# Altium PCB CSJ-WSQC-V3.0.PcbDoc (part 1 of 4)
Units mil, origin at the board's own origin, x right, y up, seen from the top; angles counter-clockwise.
Board outline 5060 x 7131.55 mil, 4 copper layers (Top Layer, InternalPlane1, InternalPlane2, Bottom Layer); 390 components, 277 nets, 1183 pads, 601 vias.
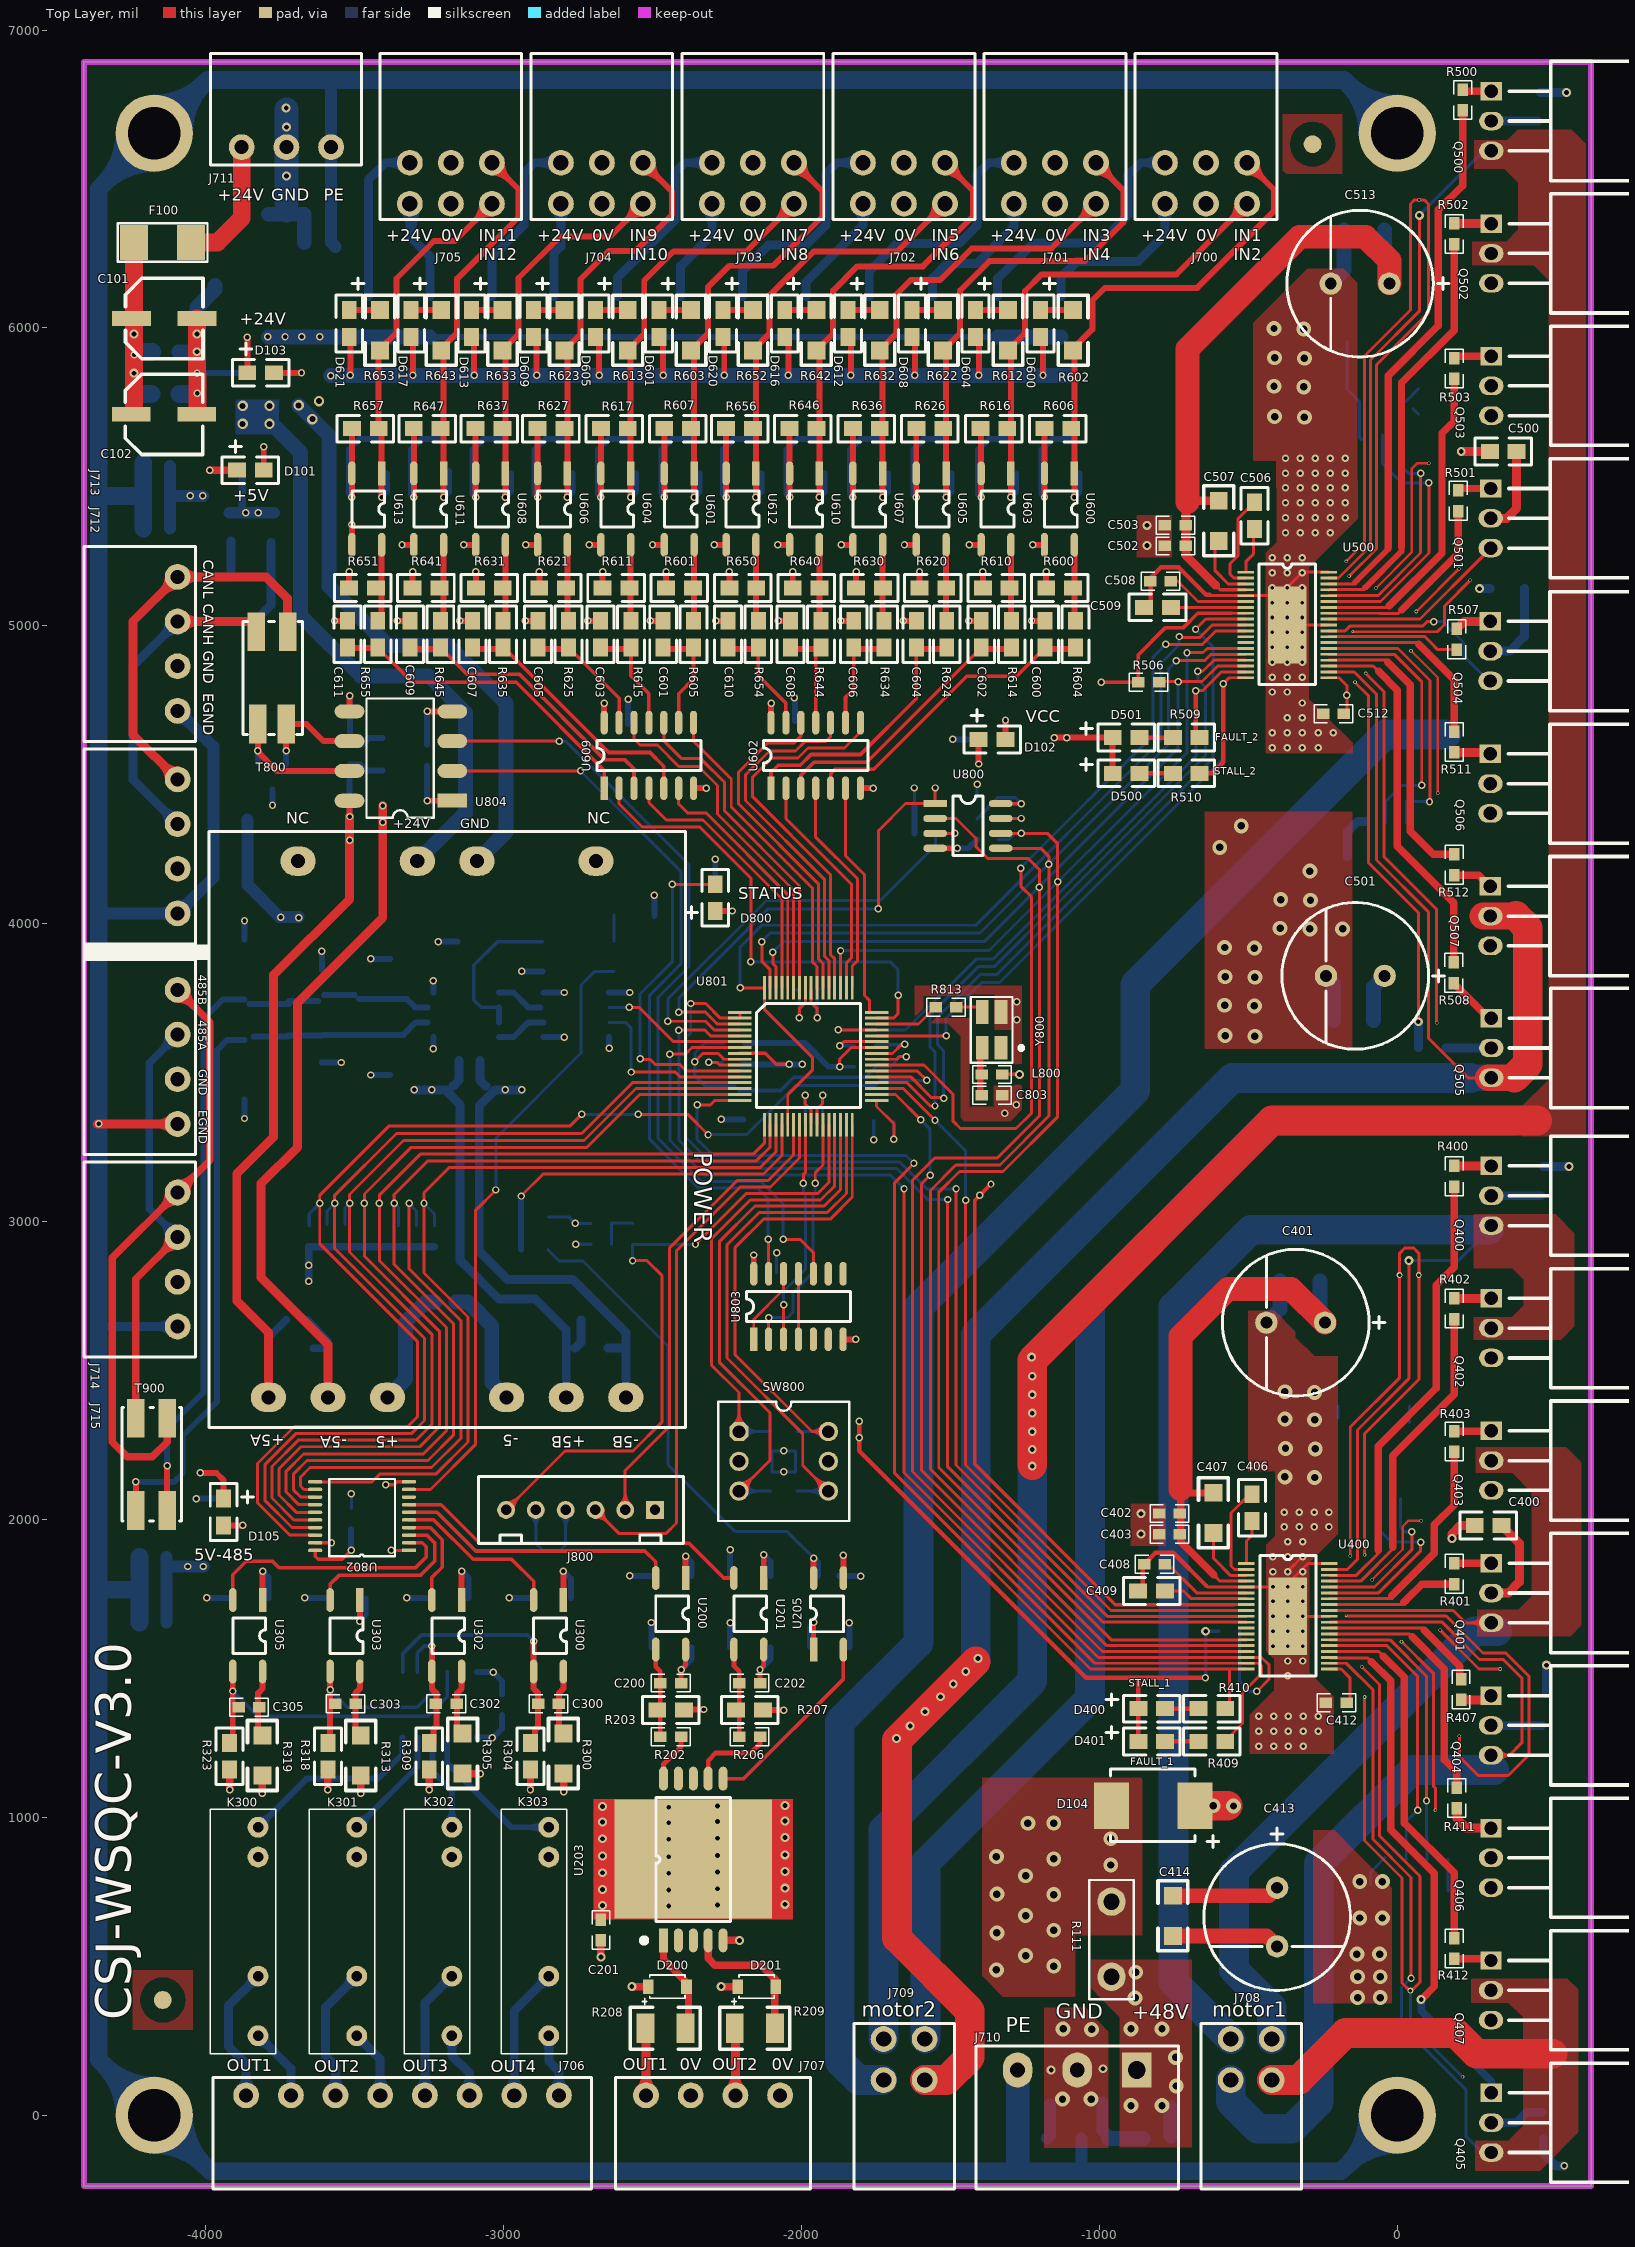
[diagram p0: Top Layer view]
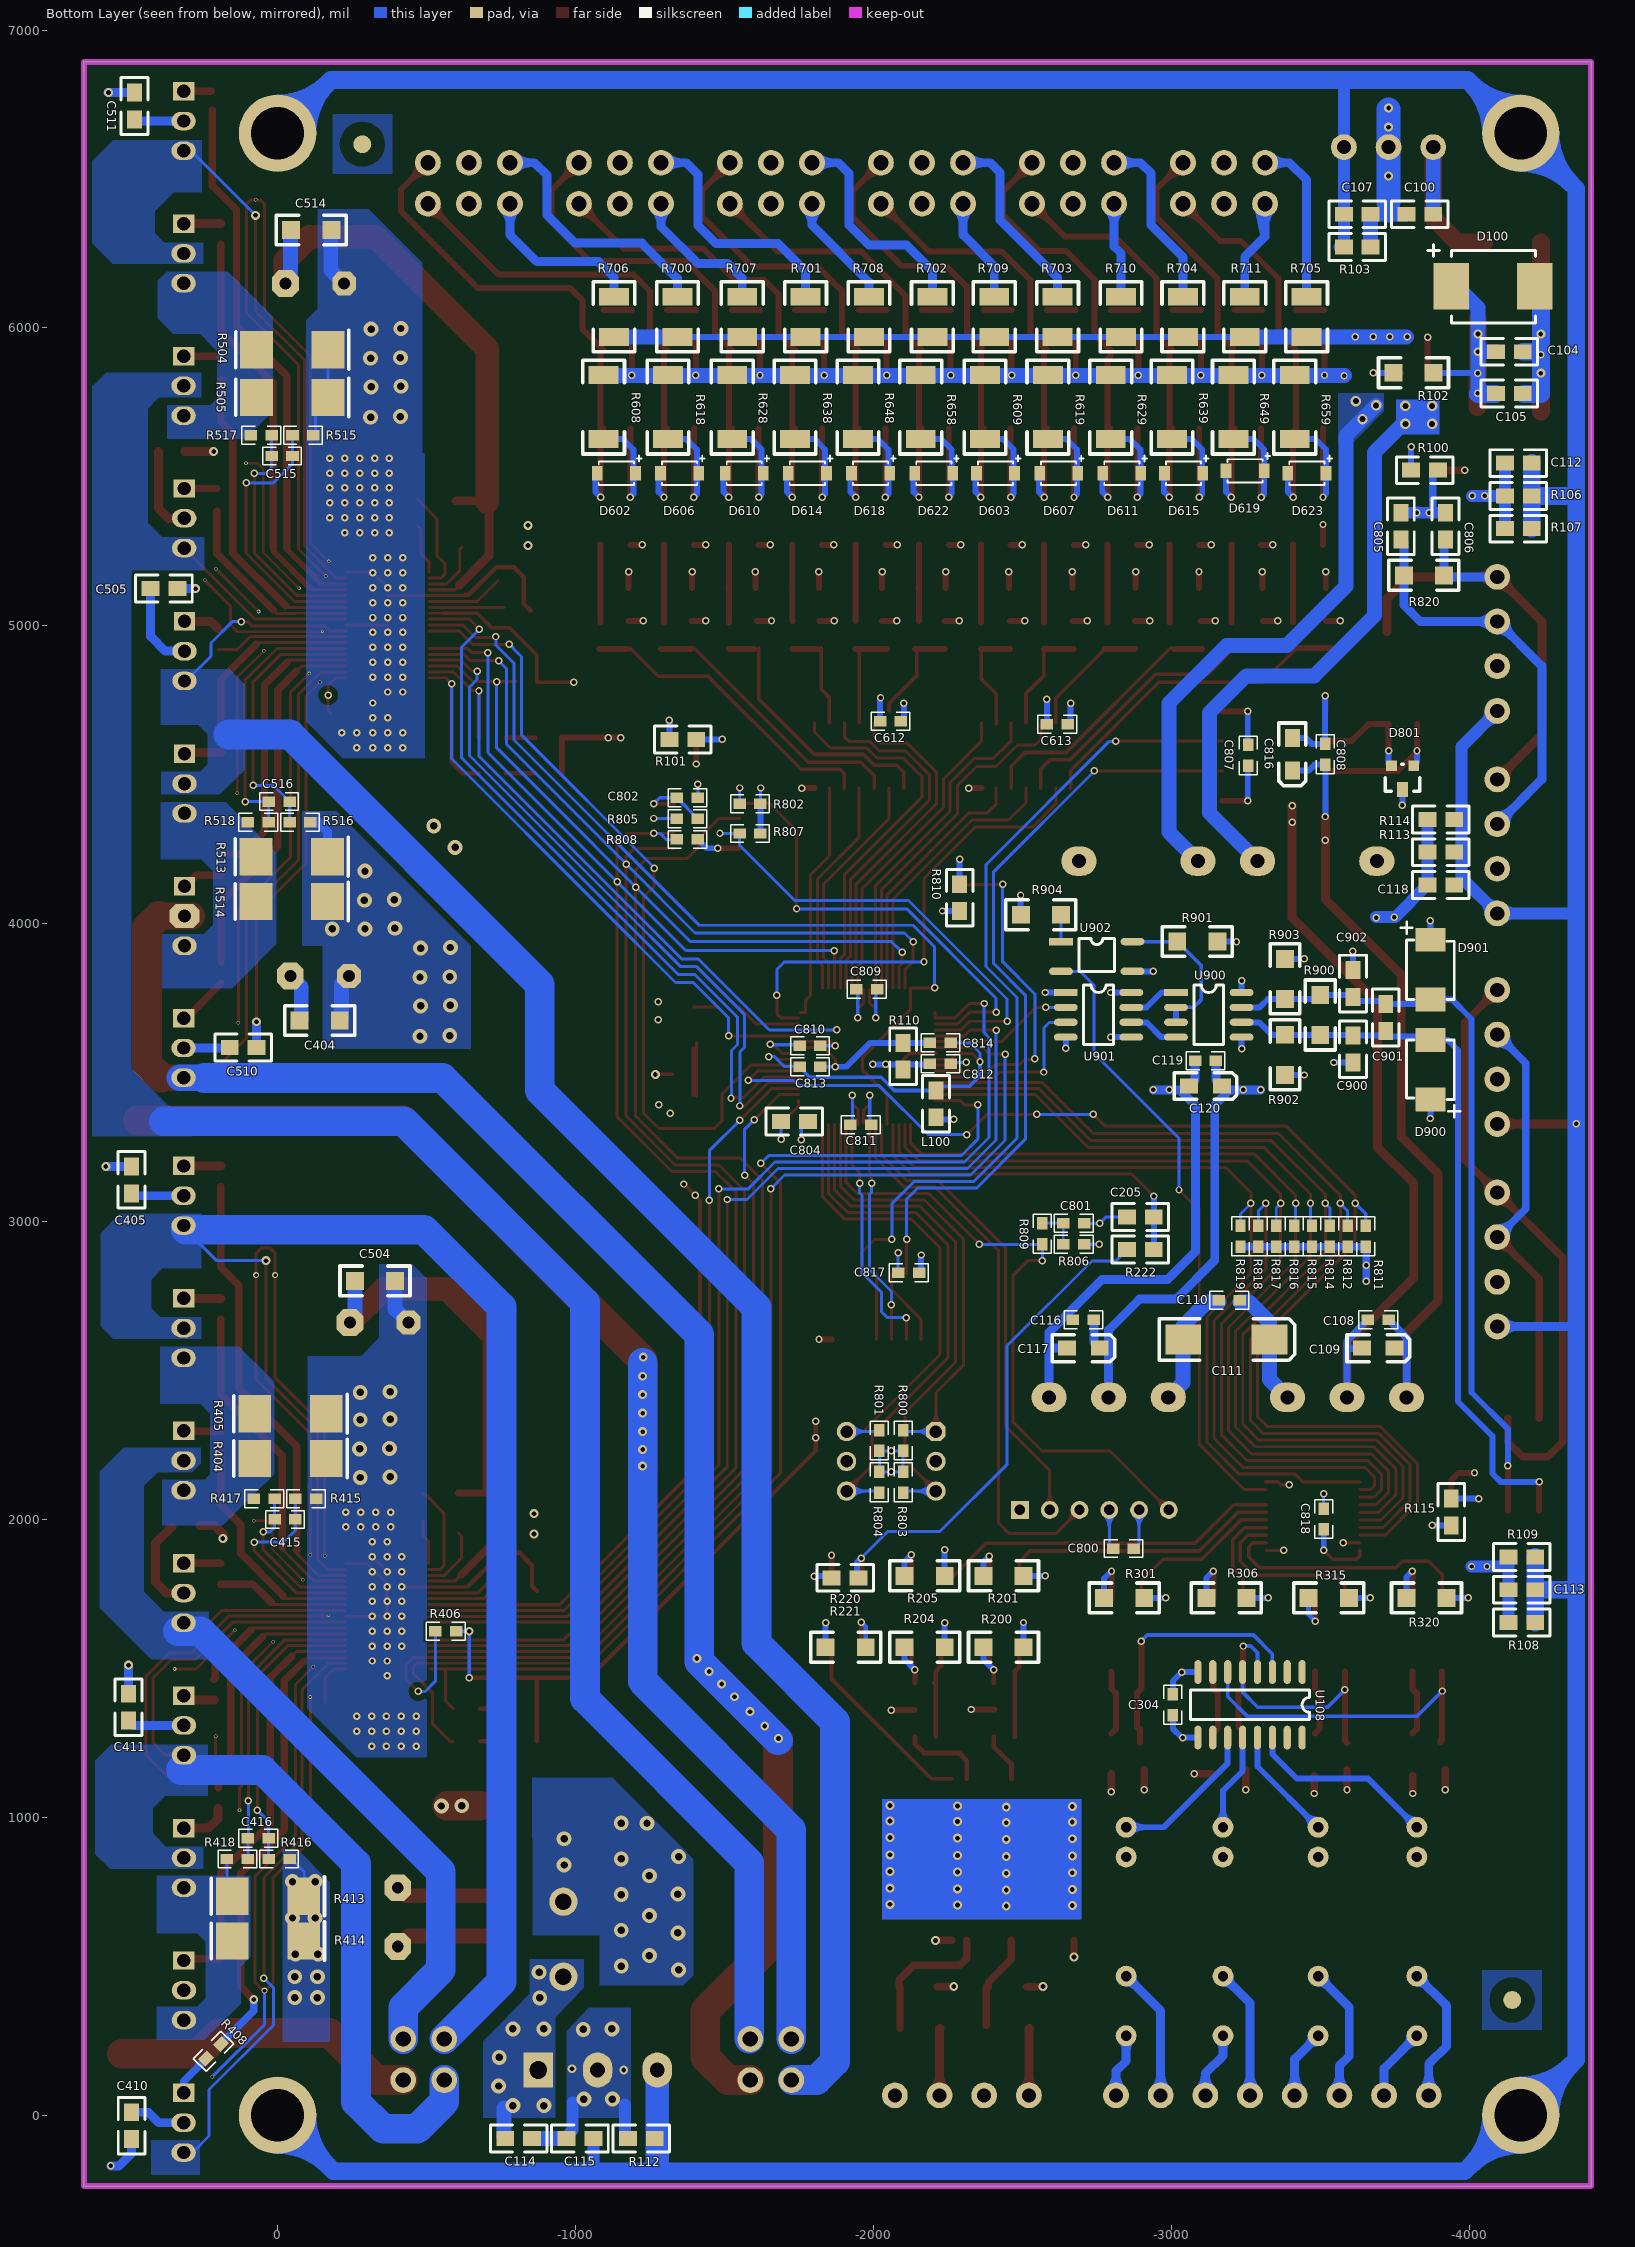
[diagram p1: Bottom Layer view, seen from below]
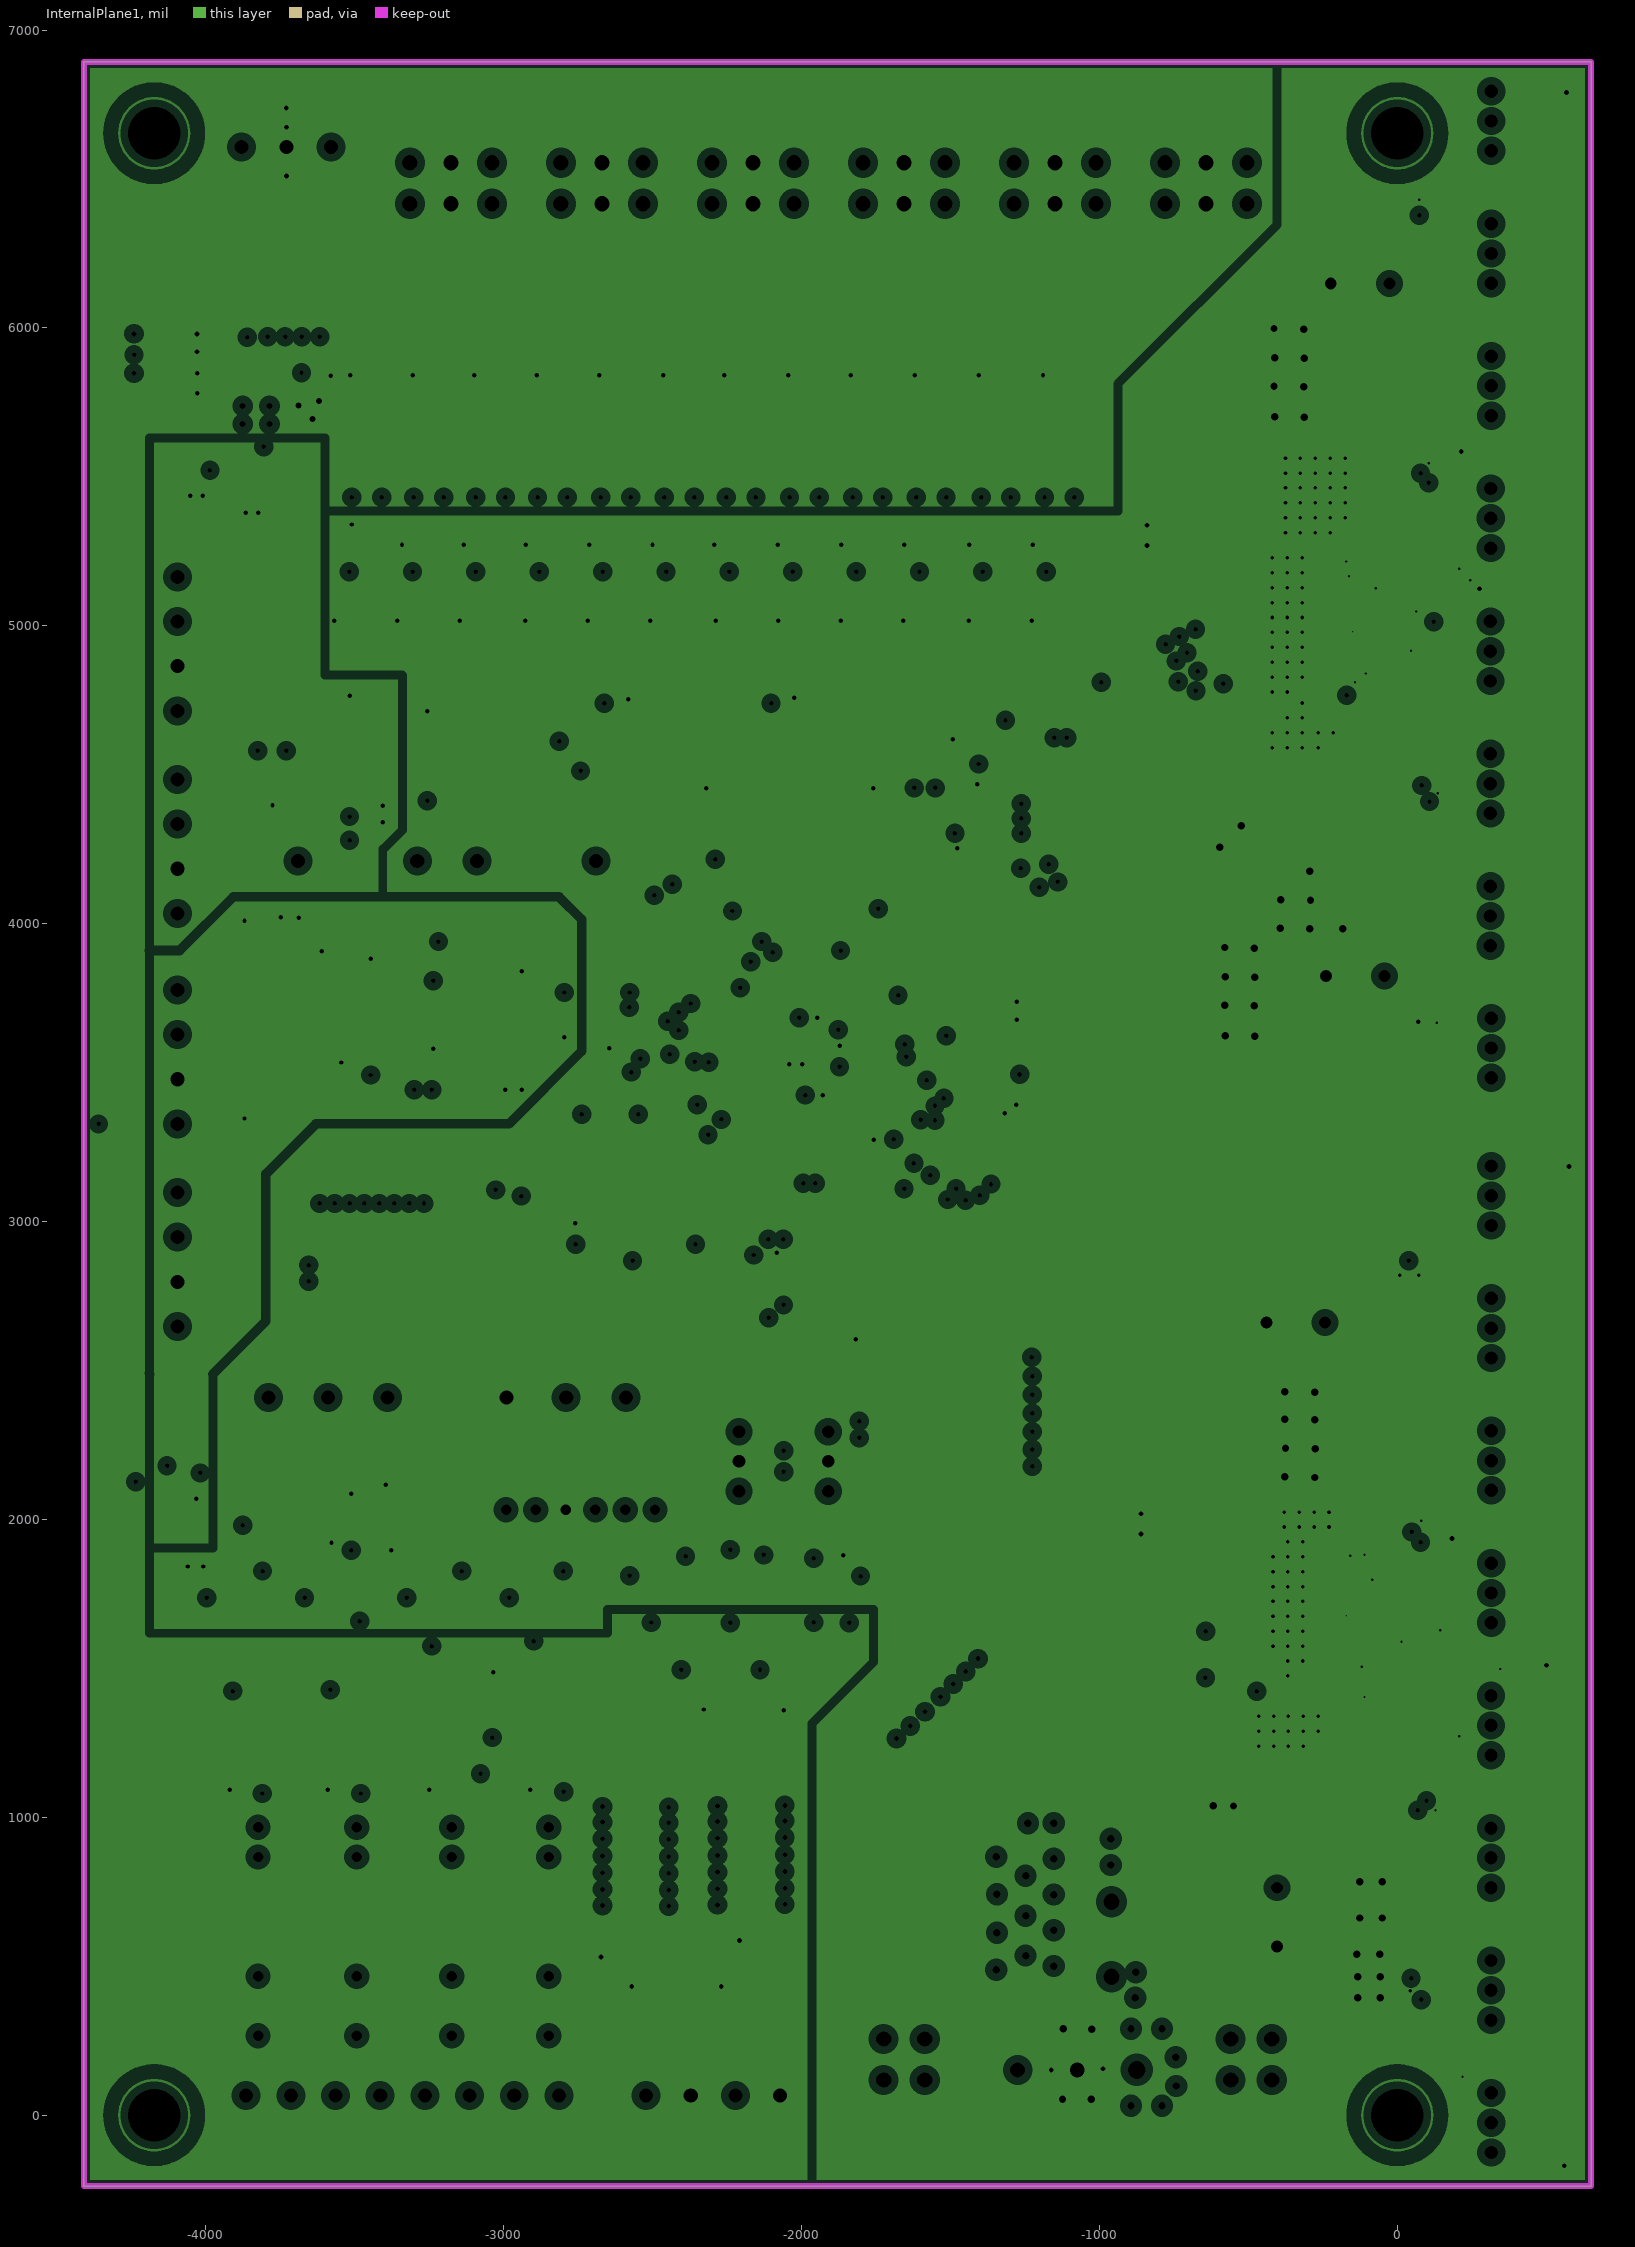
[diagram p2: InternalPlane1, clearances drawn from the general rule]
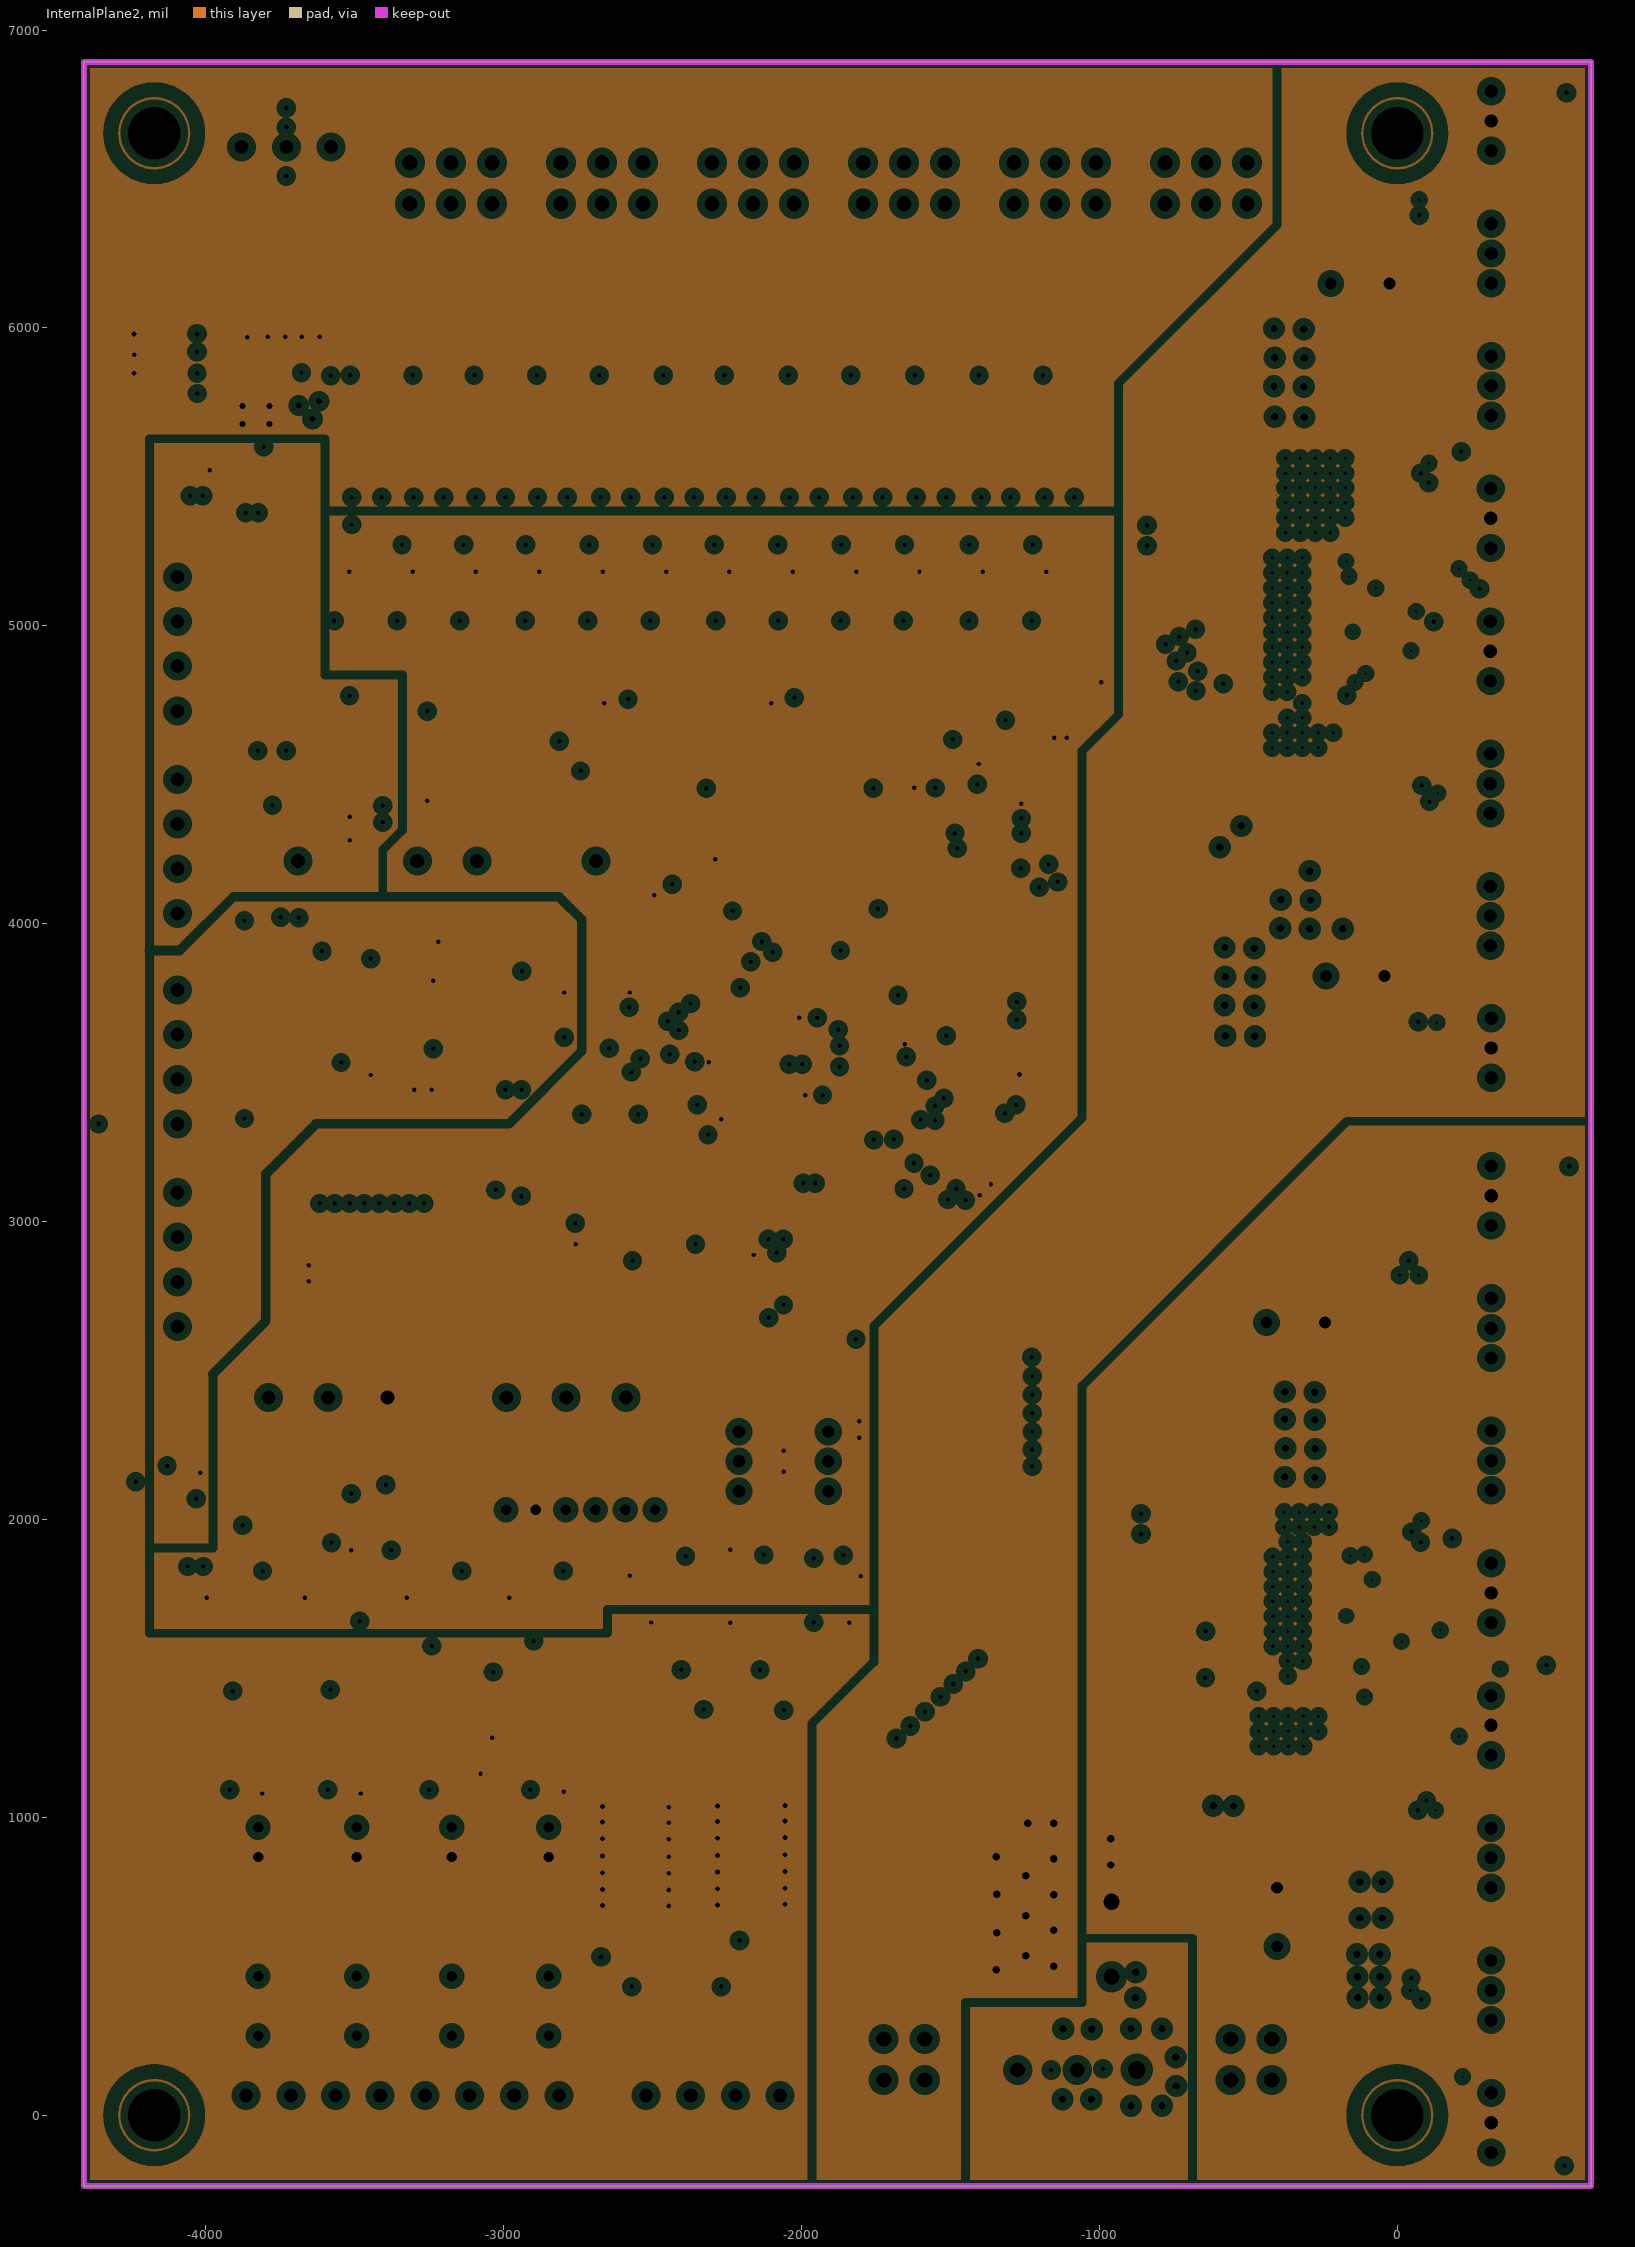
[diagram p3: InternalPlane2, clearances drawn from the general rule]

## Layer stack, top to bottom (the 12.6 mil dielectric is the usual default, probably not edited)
Top Layer: signal copper 1.4
Dielectric: core 12.6, FR-4, Dk 4.8
InternalPlane1: plane copper 1.4, net (Multiple Nets)
Dielectric: prepreg 12.6, FR-4, Dk 4.8
InternalPlane2: plane copper 1.4, net (Multiple Nets)
Dielectric: core 12.6, FR-4, Dk 4.8
Bottom Layer: signal copper 1.4

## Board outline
-4409.45,6893.28 -4409.45,-238.27 650.55,-238.27 650.55,6893.28 -4409.45,6893.28

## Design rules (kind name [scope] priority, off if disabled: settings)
Clearance Clearance_1 [HasFootprint('SOT23-5')] p1: gap=5
Clearance [All] p2: gap=8
ComponentClearance [All] p1 off: gap=10 collisioncheckmode=3 verticalgap=10 showdistances=FALSE
HoleSize [All] p1: absolutevalues=TRUE maxlimit=500 minlimit=1 maxpercent=80.000 minpercent=20.000
MinimumSolderMaskSliver [All] p1 off: minsoldermaskwidth=10
PlaneClearance [All] p1: clearance=25
PlaneConnect PlaneConnect_2 [InNet('GND')] p1: planeconnectstyle=Direct reliefexpansion=35 reliefentries=4 reliefconductorwidth=15 reliefairgap=25
PlaneConnect PlaneConnect_1 [InNet('+48V')] p2: planeconnectstyle=Direct reliefexpansion=35 reliefentries=4 reliefconductorwidth=35 reliefairgap=25
PlaneConnect [All] p3: planeconnectstyle=Relief reliefexpansion=20 reliefentries=4 reliefconductorwidth=15 reliefairgap=10
PolygonConnect [All] p1: connectstyle=Direct reliefconductorwidth=15 reliefentries=4 polygonreliefangle="90 Angle"
RoutingVias [All] p1: holewidth=15 width=25 viastyle="Through Hole" minholewidth=15 minwidth=25 maxholewidth=28 maxwidth=50
SilkToSilkClearance [All] p1 off: silktosilkclearance=1
SilkscreenOverComponentPads [All] p1 off: minsilkscreentomaskgap=10
SolderMaskExpansion [All] p1: expansion=2
Width [All] p1: maxlimit=200 minlimit=6 preferedwidth=10 minimp=50.000000 maximp=50.000000 favimp=50.000000
21 further rules are at their usual default settings.

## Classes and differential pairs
component class 485: C900 C901 C902 D900 D901 R900 R901 R902 R903 R904 T900 U900 U901 U902
component class motor2.~(38): C500 C501 C502 C503 C504 C505 C506 C507 C508 C509 C510 C511 C512 C513 C514 C515 C516 D500 D501 Q500 Q501 Q502 Q503 Q504 Q505 Q506 Q507 R500 R501 R502 R503 R504 R505 R506 R507 R508 R509 R510 R511 R512 R513 R514 R515 R516 R517 R518 U500
component class motor1.~(12): C400 C401 C402 C403 C404 C405 C406 C407 C408 C409 C410 C411 C412 C413 C414 C415 C416 D400 D401 Q400 Q401 Q402 Q403 Q404 Q405 Q406 Q407 R400 R401 R402 R403 R404 R405 R406 R407 R408 R409 R410 R411 R412 R413 R414 R415 R416 R417 R418 R424 U400
component class power: C100 C101 C102 C104 C105 C107 C108 C109 C110 C111 C112 C113 C114 C115 C116 C117 C118 C119 C120 D100 D101 D102 D103 D104 D105 F100 J100 L100 POWER R100 R101 R102 R103 R106 R107 R108 R109 R110 R111 R112 R113 R114 R115
component class port: J700 J701 J702 J703 J704 J705 J706 J707 J708 J709 J710 J711 J712 J713 J714 J715 R700 R701 R702 R703 R704 R705 R706 R707 R708 R709 R710 R711
component class pic: C800 C801 C802 C803 C804 C805 C806 C807 C808 C809 C810 C811 C812 C813 C814 C816 C817 C818 D800 D801 J800 L800 R800 R801 R802 R803 R804 R805 R806 R807 R808 R809 R810 R811 R812 R813 R814 R815 R816 R817 R818 R819 R820 SW800 T800 U800 U801 U802 U803 U804 Y800
component class output-2: C300 C302 C303 C304 C305 K300 K301 K302 K303 R300 R301 R304 R305 R306 R309 R313 R315 R318 R319 R320 R323 U108 U300 U302 U303 U305
component class output-1: C200 C201 C202 C205 D200 D201 R200 R201 R202 R203 R204 R205 R206 R207 R208 R209 R220 R221 R222 U200 U201 U203 U205
component class input: C600 C601 C602 C603 C604 C605 C606 C607 C608 C609 C610 C611 C612 C613 D600 D601 D602 D603 D604 D605 D606 D607 D608 D609 D610 D611 D612 D613 D614 D615 D616 D617 D618 D619 D620 D621 D622 D623 R600 R601 R602 R603 R604 R605 R606 R607 R608 R609 R610 R611 R612 R613 R614 R615 R616 R617 R618 R619 R620 R621 R622 R623 R624 R625 R626 R627 R628 R629 R630 R631 R632 R633 R634 R635 R636 R637 R638 R639 R640 R641 R642 R643 R644 R645 R646 R647 R648 R649 R650 R651 R652 R653 R654 R655 R656 R657 R658 R659 U600 U601 U602 U603 U604 U605 U606 U607 U608 U609 U610 U611 U612 U613

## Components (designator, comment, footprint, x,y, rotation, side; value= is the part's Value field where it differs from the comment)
C100 "103" 0805 -3879.45,6381.73 r180 bottom
C101 "100uF/50V" SMD-6.6*7.7 -4249.45,6031.73 r90 top
C102 "100uF/50V" SMD-6.6*7.7 -4250,5710 r90 top
C104 "103" 0805 -4180,5920 r180 bottom
C105 "103" 0805 -4180,5780 r180 bottom
C107 "102/200V" 0805 -3669.45,6381.73 r180 bottom
C108 "103" 0603_1 -3730,2670 r0 bottom
C109 "10uF/10V" 3216 -3700,2570 r0 bottom
C110 "103" 0603_1 -3230,2736 r0 bottom
C111 "100uF/16V" 7243 -3330,2604 r180 bottom
C112 "102/250V" 0805 -4120,5546 r0 bottom
C113 "102/250V" 0805 -4132,1764 r0 bottom
C114 "104/100V" 0805 -764,-78 r0 bottom
C115 "102/200V" 0805 -970,-78 r0 bottom
C116 "103" 0603_1 -2740,2670 r0 bottom
C117 "10uF/10V" 3216 -2710,2570 r0 bottom
C118 "102/250V" 0805 -3860,4130 r0 bottom
C119 "103" 0603_1 -3150,3540 r0 bottom
C120 "10uF/10V" 3216 -3120,3450 r0 bottom
C200 "102" 0603_1 -2404.45,1450.73 r180 top
C201 "" 0603_1 -2673.45,656.73 r270 top
C202 "102" 0603_1 -2139.45,1450.73 r180 top
C205 "102" 0805 -2851.45,3015.73 r0 bottom
C300 "102" 0603_1 -2814.45,1381.73 r180 top
C302 "102" 0603_1 -3157.78,1381.73 r180 top
C303 "102" 0603_1 -3496.11,1381.73 r180 top
C304 "104" 0603_1 -3005.45,1342.73 r90 bottom
C305 "102" 0603_1 -3820,1370 r180 top
C400 "104/100V" 0805 350,1980 r0 top
C401 "220uF/100V" "RB 5.0MM/12.5MM_NOPOST" -439.45,2660.73 r0 top
C402 "104/100V" 0603_1 -730,2020 r180 top
C403 "103" 0603_1 -730,1950 r180 top
C404 "104/100V" 1206 -73.45,3674.73 r180 bottom
C405 "104/100V" 0805 490.55,3094.73 r270 bottom
C406 "" 0805 -487.45,1994.73 r270 top
C407 "" 1206 -617.45,1954.73 r90 top
C408 "" 0603_1 -780,1850 r180 top
C409 "" 0805 -780,1760 r0 top
C410 "104/100V" 0805 490,10 r90 bottom
C411 "104/100V" 0805 500.55,1324.73 r270 bottom
C412 "" 0603_1 -169.45,1384.73 r180 top
C413 "220uF/100V" "RB 5.0MM/12.5MM_NOPOST" -403.45,566.73 r90 top
C414 "104/100V" 1206 -753.45,736.73 r270 top
C415 "102" 0603_1 -60,2000 r0 bottom
C416 "102" 0603_1 30,930 r0 bottom
C500 "104/100V" 0805 400.55,5584.73 r0 top
C501 "220uF/100V" "RB 5.0MM/12.5MM_NOPOST" -239.45,3824.73 r0 top
C502 "104" 0603_1 -710,5268 r180 top
C503 "103" 0603_1 -710,5338 r180 top
C504 "104/100V" 1206 -259.45,2800.73 r180 bottom
C505 "104/100V" 0805 426.55,5124.73 r0 bottom
C506 "" 0805 -479.45,5324.73 r270 top
C507 "" 1206 -599.45,5284.73 r90 top
C508 "" 0603_1 -760,5150 r180 top
C509 "" 0805 -760,5062 r0 top
C510 "104/100V" 0805 160.55,3584.73 r0 bottom
C511 "104/100V" 0805 480,6700 r270 bottom
C512 "" 0603_1 -179.45,4704.73 r180 top
C513 "220uF/100V" "RB 5.0MM/12.5MM_NOPOST" -223.45,6148.73 r0 top
C514 "104/100V" 1206 -45.45,6328.73 r180 bottom
C515 "102" 0603_1 -50,5570 r0 bottom
C516 "102" 0603_1 -40,4410 r0 bottom
C600 "102" 0805 -1182.62,5016.73 r90 top
C601 "102" 0805 -2464.62,5016.73 r90 top
C602 "102" 0805 -1396.62,5016.73 r90 top
C603 "102" 0805 -2674.62,5016.73 r90 top
C604 "102" 0805 -1614.62,5016.73 r90 top
C605 "102" 0805 -2884.62,5016.73 r90 top
C606 "102" 0805 -1824.62,5016.73 r90 top
C607 "102" 0805 -3104.62,5016.73 r90 top
C608 "102" 0805 -2036.62,5016.73 r90 top
C609 "102" 0805 -3314.62,5016.73 r90 top
C610 "102" 0805 -2246.62,5016.73 r90 top
C611 "102" 0805 -3524.62,5016.73 r90 top
C612 "104" 0603_1 -2092.45,4679.73 r0 bottom
C613 "104" 0603_1 -2652.45,4669.73 r0 bottom
C800 "104" 0603_1 -2804.55,1902.27 r180 bottom
C801 "104" 0603_1 -2637.45,2993.73 r180 bottom
C802 "104" 0603_1 -1340.62,4422.73 r180 bottom
C803 "103" 0603_1 -1395.45,3423.73 r0 top
C804 "10uF" 0805 -1690,3336 r0 bottom
C805 "22pF" 0805 -3770.73,5379.38 r90 bottom
C806 "22pF" 0805 -3920.73,5289.38 r270 bottom
C807 "104" 0603_1 -3258,4530 r90 bottom
C808 "104" 0603_1 -3516.45,4533.73 r90 bottom
C809 "104" 0603_1 -2012.45,3779.73 r0 bottom
C810 "104" 0603_1 -1752.45,3589.73 r180 bottom
C811 "104" 0603_1 -1992.45,3324.73 r0 bottom
C812 "104" 0603_1 -2260,3530 r0 bottom
C813 "104" 0603_1 -1752.45,3519.73 r180 bottom
C814 "104" 0603_1 -2260,3600 r0 bottom
C816 "10uF/10V" 3216 -3401.45,4563.73 r90 bottom
C817 "104" 0603_1 -2153.45,2827.73 r0 bottom
C818 "104" 0603_1 -3511.55,1966.27 r90 bottom
C900 "220pF" 0805 -3610,3534 r270 bottom
C901 "220pF" 0805 -3720,3640 r270 bottom
C902 "220pF" 0805 -3610,3844 r90 bottom
D100 "SMCJ26A" DO-214AB -3940,6140 r0 bottom
D101 "LED0" 0805_2 -3895.38,5522.44 r0 top
D102 "LED0" 0805_2 -1405.38,4618.44 r0 top
D103 "LED0" 0805_2 -3860.73,5849.38 r0 top
D104 "SMCJ54A" DO-214AB -679.45,1038.73 r0 top
D105 "LED0" 0805_2 -3940,2070 r270 top
D200 "MBR0540T1" SOD-123 -2514.45,431.73 r0 top
D201 "MBR0540T1" SOD-123 -2214.45,431.73 r0 top
D400 "STALL" 0805_1 -869.45,1364.73 r0 top
D401 "FAULTn" 0805_1 -869.45,1254.73 r0 top
D500 "STALL" 0805_1 -955.45,4504.73 r0 top
D501 "FAULTn" 0805_1 -955.45,4624.73 r0 top
D600 "LED" 0805_1 -1197.45,6059.73 r270 top
D601 "LED" 0805_1 -2478.45,6059.73 r270 top
D602 "MMSD4148T1G" SOD-123 -1201.32,5511.73 r0 bottom
D603 "MMSD4148T1G" SOD-123 -2473.93,5511.73 r0 bottom
D604 "LED" 0805_1 -1416.45,6059.73 r270 top
D605 "LED" 0805_1 -2691.45,6059.73 r270 top
D606 "MMSD4148T1G" SOD-123 -1413.42,5511.73 r0 bottom
D607 "MMSD4148T1G" SOD-123 -2686.04,5511.73 r0 bottom
D608 "LED" 0805_1 -1629.45,6059.73 r270 top
D609 "LED" 0805_1 -2899.45,6059.73 r270 top
D610 "MMSD4148T1G" SOD-123 -1630.52,5511.73 r0 bottom
D611 "MMSD4148T1G" SOD-123 -2898.14,5511.73 r0 bottom
D612 "LED" 0805_1 -1844.45,6059.73 r270 top
D613 "LED" 0805_1 -3107.45,6059.73 r270 top
D614 "MMSD4148T1G" SOD-123 -1842.62,5511.73 r0 bottom
D615 "MMSD4148T1G" SOD-123 -3105.24,5511.73 r0 bottom
D616 "LED" 0805_1 -2056.45,6059.73 r270 top
D617 "LED" 0805_1 -3310.45,6059.73 r270 top
D618 "MMSD4148T1G" SOD-123 -2054.73,5511.73 r0 bottom
D619 "MMSD4148T1G" SOD-123 -3311.72,5520 r0 bottom
D620 "LED" 0805_1 -2263.45,6059.73 r270 top
D621 "LED" 0805_1 -3518.45,6059.73 r270 top
D622 "MMSD4148T1G" SOD-123 -2266.83,5511.73 r0 bottom
D623 "MMSD4148T1G" SOD-123 -3519.45,5511.73 r0 bottom
D800 "" 0805_2 -2289.73,4042.55 r90 top
D801 "SP0502BAJT" SOT-23-DIODE -3814,4530 r180 bottom
D900 "SMAJ8.0A" D214A -3870,3510 r90 bottom
D901 "SMAJ8.0A" D214A -3870,3846 r270 bottom
F100 "FUSE2" 157T -4049.45,6286.73 r180 top
J700 "MCDN 1.5/3-G1-3.5 P14THR" MCDN-3 -504.45,6416.73 r180 top locked
J701 "MCDN 1.5/3-G1-3.5 P14THR" MCDN-3 -1011.45,6416.73 r180 top locked
J702 "MCDN 1.5/3-G1-3.5 P14THR" MCDN-3 -1518.45,6416.73 r180 top locked
J703 "MCDN 1.5/3-G1-3.5 P14THR" MCDN-3 -2025.45,6416.73 r180 top locked
J704 "MCDN 1.5/3-G1-3.5 P14THR" MCDN-3 -2532.45,6416.73 r180 top locked
J705 "MCDN 1.5/3-G1-3.5 P14THR" MCDN-3 -3039.45,6416.73 r180 top locked
J706 "MC 1.5/8-G-3.81" "MC 1.5/8-G-3.81" -3864.45,66.73 r0 top locked
J707 "MC 1.5/4-G-3.81" "MC 1.5/4-G-3.81" -2624.45,66.73 r0 top locked
J708 "CON4" MCDN-2 -559.45,255.71 r0 top locked
J709 "CON4" MCDN-2 -1724.45,255.71 r0 top locked
J710 "CON3" DECA-3 -1274.45,151.77 r180 top locked
J711 "CON3" "MC 1.5/3-G-3.81" -3579.45,6606.73 r180 top
J712 "MC 1.5/4-G-3.81" "MC 1.5/4-G-3.81" -4094.45,4586.73 r270 top
J713 "MC 1.5/4-G-3.81" "MC 1.5/4-G-3.81" -4094.45,5266.73 r270 top locked
J714 "MC 1.5/4-G-3.81" "MC 1.5/4-G-3.81" -4094.45,3880 r270 top locked
J715 "MC 1.5/4-G-3.81" "MC 1.5/4-G-3.81" -4094.45,3200 r270 top locked
J800 "PICkit_2" DIP6 -2492,2032 r180 top locked
K300 "PA1A-24V" RYPA1A-24 -3824.45,266.73 r0 top
K301 "PA1A-24V" RYPA1A-24 -3493.11,266.73 r0 top
K302 "PA1A-24V" RYPA1A-24 -3173.78,266.73 r0 top
K303 "PA1A-24V" RYPA1A-24 -2848.45,266.73 r0 top
L100 "0R" 0805 -2210,3350 r270 bottom
L800 "" 0603_1 -1325.45,3493.73 r180 top
POWER "ZDL10-24T050505" ZDL10-24T050505 -3690,4210 r270 top locked
Q400 "MOSFET N" TO-220 315.55,2986.64 r270 top
Q401 "MOSFET N" TO-220 315.55,1652.96 r270 top
Q402 "MOSFET N" TO-220 315.55,2542.08 r270 top
Q403 "MOSFET N" TO-220 315.55,2097.52 r270 top
Q404 "MOSFET N" TO-220 314.55,1208.41 r270 top
Q405 "MOSFET N" TO-220 315.55,-125.27 r270 top
Q406 "MOSFET N" TO-220 314.55,763.85 r270 top
Q407 "MOSFET N" TO-220 314.55,319.29 r270 top
Q500 "MOSFET N" TO-220 315.55,6594.53 r270 top
Q501 "MOSFET N" TO-220 313.55,5260.85 r270 top
Q502 "MOSFET N" TO-220 315.55,6149.97 r270 top
Q503 "MOSFET N" TO-220 315.55,5705.41 r270 top
Q504 "MOSFET N" TO-220 312.55,4814.73 r270 top
Q505 "MOSFET N" TO-220 315.55,3482.62 r270 top
Q506 "MOSFET N" TO-220 312.55,4370.17 r270 top
Q507 "MOSFET N" TO-220 312.55,3925.62 r270 top
R100 "1.2K" 0805 -3805.38,5522.44 r0 bottom
R101 "1.2K" 0805 -1315.38,4618.44 r0 bottom
R102 "5.6K" 1206 -3745.73,5849.38 r180 bottom
R103 "1M" 0805 -3669.45,6271.73 r180 bottom
R106 "0R" 0805 -4210,5436 r180 bottom
R107 "1M" 0805 -4120,5326 r0 bottom
R108 "0R" 0805 -4222,1654 r180 bottom
R109 "1M" 0805 -4132,1874 r0 bottom
R110 "0R" 0805 -2100,3510 r270 bottom
R111 "PTC Resettable Fuses MF-R800 BOURNS" RAD-0.3 -959.45,464.73 r0 top
R112 "1M" 0805 -1176,-78 r0 bottom
R113 "0R" 0805 -3950,4240 r180 bottom
R114 "1M" 0805 -3860,4350 r0 bottom
R115 "1.2K" 0805 -3940,1980 r270 bottom
R200 "3.3K" 1206 -2504.45,1570.73 r0 bottom
R201 "470R" 1206 -2369.45,1810.73 r180 bottom
R202 "2K" 0603_1 -2474.45,1270.73 r0 top
R203 "1.5K" 0805 -2394.45,1360.73 r0 top
R204 "3.3K" 1206 -2239.45,1570.73 r0 bottom
R205 "470R" 1206 -2104.45,1810.73 r180 bottom
R206 "2K" 0603_1 -2209.45,1270.73 r0 top
R207 "1.5K" 0805 -2129.45,1360.73 r0 top
R208 "1210L010" 1210_1 -2524.45,291.73 r0 top
R209 "1210L010" 1210_1 -2224.45,291.73 r0 top
R220 "2K" 0805 -1860,1804 r0 bottom
R221 "5.6K" 1206 -1974.45,1570.73 r0 bottom
R222 "2K" 0805 -2851.45,2905.73 r0 bottom
R300 "3.3K" 1206 -2799.45,1146.73 r90 top
R301 "470R" 1206 -2774.45,1736.73 r180 bottom
R304 "1.5K" 0805 -2910,1160 r270 top
R305 "3.3K" 1206 -3137.78,1146.73 r90 top
R306 "470R" 1206 -3117.78,1736.73 r180 bottom
R309 "1.5K" 0805 -3250,1160 r270 top
R313 "3.3K" 1206 -3480,1140 r90 top
R315 "470R" 1206 -3461.11,1736.73 r180 bottom
R318 "1.5K" 0805 -3590,1160 r270 top
R319 "3.3K" 1206 -3810,1140 r90 top
R320 "470R" 1206 -3789.45,1736.73 r180 bottom
R323 "1.5K" 0805 -3920,1160 r270 top
R400 "" 0603_1 190.55,3116.73 r90 top
R401 "" 0603_1 190.55,1852.73 r270 top
R402 "" 0603_1 190.55,2672.73 r90 top
R403 "" 0603_1 190.55,2296.73 r270 top
R404 "0.068R" 2512_1 -163.45,2204.73 r0 bottom
R405 "0.068R" 2512_1 -163.45,2354.73 r0 bottom
R406 "" 0603_1 -599.45,1624.73 r0 bottom
R407 "" 0603_1 214,1464 r270 top
R408 "" 0603_1 240,190 r135 bottom
R409 "1.5K" 0805 -577.45,1254.73 r0 top
R410 "1.5K" 0805 -577.45,1364.73 r0 top
R411 "" 0603_1 200,1100 r270 top
R412 "" 0603_1 190.55,524.73 r90 top
R413 "0.068R" 2512_1 -87.45,734.73 r0 bottom
R414 "0.068R" 2512_1 -87.45,584.73 r0 bottom
R415 "" 0603_1 -60,2070 r180 bottom
R416 "" 0603_1 30,860 r180 bottom
R417 "" 0603_1 10,2070 r0 bottom
R418 "" 0603_1 100,860 r0 bottom
R500 "" 0603_1 220,6730 r90 top
R501 "" 0603_1 204.55,5454.73 r270 top
R502 "" 0603_1 190.55,6280.73 r90 top
R503 "" 0603_1 190.55,5898.73 r270 top
R504 "0.068R" 2512_1 -169.45,5926.73 r0 bottom
R505 "0.068R" 2512_1 -169.45,5766.73 r0 bottom
R506 "" 0603_1 -870,4810 r0 top
R507 "" 0603_1 200,4920 r90 top
R508 "" 0603_1 190,3800 r90 top
R509 "1.5K" 0805 -663.45,4624.73 r0 top
R510 "1.5K" 0805 -663.45,4504.73 r0 top
R511 "" 0603_1 190.55,4644.73 r270 top
R512 "" 0603_1 190.55,4162.73 r90 top
R513 "0.068R" 2512_1 -167.45,4224.73 r0 bottom
R514 "0.068R" 2512_1 -167.45,4074.73 r0 bottom
R515 "" 0603_1 -50,5640 r180 bottom
R516 "" 0603_1 -40,4340 r180 bottom
R517 "" 0603_1 20,5640 r0 bottom
R518 "" 0603_1 30,4340 r0 bottom
R600 "2K" 0805 -1088.62,5126.73 r0 top
R601 "2K" 0805 -2364.99,5126.73 r0 top
R602 "5.6K" 1206 -1088.45,5924.73 r90 top
R603 "5.6K" 1206 -2370.81,5924.73 r90 top
R604 "2K" 0805 -1080.62,5016.73 r90 top
R605 "2K" 0805 -2362.62,5016.73 r90 top
R606 "1K" 0805 -1094.45,5661.73 r0 top
R607 "1K" 0805 -2370.81,5661.73 r0 top
R608 "3.3K" 2010 -1094.45,5626.73 r90 bottom
R609 "3.3K" 2010 -2374.9,5626.73 r90 bottom
R610 "2K" 0805 -1301.35,5126.73 r0 top
R611 "2K" 0805 -2577.71,5126.73 r0 top
R612 "5.6K" 1206 -1307.18,5924.73 r90 top
R613 "5.6K" 1206 -2583.54,5924.73 r90 top
R614 "2K" 0805 -1294.62,5016.73 r90 top
R615 "2K" 0805 -2572.62,5016.73 r90 top
R616 "1K" 0805 -1309.45,5661.73 r0 top
R617 "1K" 0805 -2583.54,5661.73 r0 top
R618 "3.3K" 2010 -1310.36,5626.73 r90 bottom
R619 "3.3K" 2010 -2585.81,5626.73 r90 bottom
R620 "2K" 0805 -1514.08,5126.73 r0 top
R621 "2K" 0805 -2790.44,5126.73 r0 top
R622 "5.6K" 1206 -1524.9,5924.73 r90 top
R623 "5.6K" 1206 -2796.27,5924.73 r90 top
R624 "2K" 0805 -1512.62,5016.73 r90 top
R625 "2K" 0805 -2782.62,5016.73 r90 top
R626 "1K" 0805 -1524.45,5661.73 r0 top
R627 "1K" 0805 -2796.27,5661.73 r0 top
R628 "3.3K" 2010 -1526.27,5626.73 r90 bottom
R629 "3.3K" 2010 -2796.72,5626.73 r90 bottom
R630 "2K" 0805 -1726.8,5126.73 r0 top
R631 "2K" 0805 -3003.17,5126.73 r0 top
R632 "5.6K" 1206 -1737.63,5924.73 r90 top
R633 "5.6K" 1206 -3003.99,5924.73 r90 top
R634 "2K" 0805 -1722.62,5016.73 r90 top
R635 "2K" 0805 -3002.62,5016.73 r90 top
R636 "1K" 0805 -1737.63,5661.73 r0 top
R637 "1K" 0805 -3003.99,5661.73 r0 top
R638 "3.3K" 2010 -1737.18,5626.73 r90 bottom
R639 "3.3K" 2010 -3002.63,5626.73 r90 bottom
R640 "2K" 0805 -1939.53,5126.73 r0 top
R641 "2K" 0805 -3215.89,5126.73 r0 top
R642 "5.6K" 1206 -1950.36,5924.73 r90 top
R643 "5.6K" 1206 -3209.72,5924.73 r90 top
R644 "2K" 0805 -1934.36,5016.73 r90 top
R645 "2K" 0805 -3212.62,5016.73 r90 top
R646 "1K" 0805 -1950.36,5661.73 r0 top
R647 "1K" 0805 -3211.72,5661.73 r0 top
R648 "3.3K" 2010 -1948.08,5626.73 r90 bottom
R649 "3.3K" 2010 -3208.54,5626.73 r90 bottom
R650 "2K" 0805 -2152.26,5126.73 r0 top
R651 "2K" 0805 -3428.62,5126.73 r0 top
R652 "5.6K" 1206 -2163.08,5924.73 r90 top
R653 "5.6K" 1206 -3415.45,5924.73 r90 top
R654 "2K" 0805 -2145.08,5016.73 r90 top
R655 "2K" 0805 -3422.62,5016.73 r90 top
R656 "1K" 0805 -2163.08,5661.73 r0 top
R657 "1K" 0805 -3419.45,5661.73 r0 top
R658 "3.3K" 2010 -2158.99,5626.73 r90 bottom
R659 "3.3K" 2010 -3414.45,5626.73 r90 bottom
R700 "1210L010" 1210_1 -1342.18,6104.73 r270 bottom
R701 "1210L010" 1210_1 -1772.63,6104.73 r270 bottom
R702 "1210L010" 1210_1 -2198.08,6104.73 r270 bottom
R703 "1210L010" 1210_1 -2618.54,6104.73 r270 bottom
R704 "1210L010" 1210_1 -3038.99,6104.73 r270 bottom
R705 "1210L010" 1210_1 -3454.45,6104.73 r270 bottom
R706 "1210L010" 1210_1 -1129.45,6104.73 r270 bottom
R707 "1210L010" 1210_1 -1559.9,6104.73 r270 bottom
R708 "1210L010" 1210_1 -1985.36,6104.73 r270 bottom
R709 "1210L010" 1210_1 -2405.81,6104.73 r270 bottom
R710 "1210L010" 1210_1 -2831.27,6104.73 r270 bottom
R711 "1210L010" 1210_1 -3246.72,6104.73 r270 bottom
R800 "4.7K" 0603_1 -2100,2300 r270 bottom
R801 "4.7K" 0603_1 -2020,2230 r90 bottom
R802 "10K" 0603_1 -1620.62,4402.73 r0 bottom
R803 "4.7K" 0603_1 -2100,2090 r90 bottom
R804 "4.7K" 0603_1 -2020,2160 r270 bottom
R805 "10K" 0603_1 -1410.62,4352.73 r0 bottom
R806 "10K" 0603_1 -2637.45,2923.73 r180 bottom
R807 "10K" 0603_1 -1620.62,4302.73 r0 bottom
R808 "10K" 0603_1 -1340.62,4282.73 r180 bottom
R809 "470R" 0603_1 -2567.45,2993.73 r270 bottom
R810 "1.2K" 0805 -2289.73,4042.55 r270 bottom
R811 "5.6K" 0603_1 -3652.45,2985.73 r270 bottom
R812 "5.6K" 0603_1 -3592.45,2985.73 r270 bottom
R813 "33" 0603_1 -1550,3720 r0 top
R814 "5.6K" 0603_1 -3532.45,2985.73 r270 bottom
R815 "5.6K" 0603_1 -3472.45,2985.73 r270 bottom
R816 "5.6K" 0603_1 -3412.45,2985.73 r270 bottom
R817 "5.6K" 0603_1 -3352.45,2985.73 r270 bottom
R818 "5.6K" 0603_1 -3292.45,2985.73 r270 bottom
R819 "5.6K" 0603_1 -3232.45,2985.73 r270 bottom
R820 "120" 1206 -3780.73,5169.38 r180 bottom
R900 "120" 1206 -3500,3626 r90 bottom
R901 "2k" 1206 -3020,3940 r180 bottom
R902 "4.7K" 1206 -3382,3492 r90 bottom
R903 "4.7K" 1206 -3382,3882 r270 bottom
R904 "470R" 1206 -2630,4030 r0 bottom
SW800 "SW DIP-3" DIP-6 -1950,2240 r0 top
T800 "744227" WE-CMB#1 -3730,4670 r90 top
T900 "744227" WE-CMB#2 -4130,2030 r90 top
U108 "ULN2003" SOP16 -3439.45,1487.73 r270 bottom
U200 "HCPL181" SOP-4-2 -2389.45,1803.53 r270 top
U201 "HCPL181" SOP-4-2 -2126.95,1803.53 r270 top
U203 "VN340SP" SOP10 -2463.45,586.73 r90 top
U205 "HCPL181" SOP-4-2 -1959.45,1562.94 r90 top
U300 "HCPL181" SOP-4-2 -2799.45,1729.53 r270 top
U302 "HCPL181" SOP-4-2 -3141.11,1729.53 r270 top
U303 "HCPL181" SOP-4-2 -3482.78,1729.53 r270 top
U305 "HCPL181" SOP-4-2 -3809.45,1729.53 r270 top
U400 "DRV8711" SOP38 -367.45,1674.73 r0 top
U500 "DRV8711" SOP38 -369.45,5002.73 r0 top
U600 "HCPL-181" SOP-4-2 -1084.45,5511.73 r270 top
U601 "HCPL-181" SOP-4-2 -2360.81,5511.73 r270 top
U602 "74LS14" SOP14 -2102.45,4454.73 r90 top
U603 "HCPL-181" SOP-4-2 -1297.18,5511.73 r270 top
U604 "HCPL-181" SOP-4-2 -2573.54,5511.73 r270 top
U605 "HCPL-181" SOP-4-2 -1514.9,5511.73 r270 top
U606 "HCPL-181" SOP-4-2 -2786.27,5511.73 r270 top
U607 "HCPL-181" SOP-4-2 -1727.63,5511.73 r270 top
U608 "HCPL-181" SOP-4-2 -2993.99,5511.73 r270 top
U609 "74LS14" SOP14 -2662.45,4454.73 r90 top
U610 "HCPL-181" SOP-4-2 -1940.36,5511.73 r270 top
U611 "HCPL-181" SOP-4-2 -3201.72,5511.73 r270 top
U612 "HCPL-181" SOP-4-2 -2153.08,5511.73 r270 top
U613 "HCPL-181" SOP-4-2 -3409.45,5511.73 r270 top
U800 "M95M01RMN6TP" SO-8 -1437.45,4334.17 r0 top
U801 "PIC18F66K80" TQFP-64 -2201.86,3702.37 r0 top locked
U802 "74LS245A" SSO-20 -3318,1896 r90 top
U803 "74LS14" SOP14 -2160.45,2604.73 r90 top
U804 "ISO1050" DUB-8 -3351.45,4493.73 r180 top locked
U900 "MAX485CSA" SO-8 -3130,3700 r180 bottom
U901 "ISO7221C" SO-8 -2760,3700 r180 bottom
U902 "HCPL181" SOP-4-2 -2630,3940 r180 bottom
Y800 "8M" CRYSTAL-SMD -1330.45,3583.73 r0 top

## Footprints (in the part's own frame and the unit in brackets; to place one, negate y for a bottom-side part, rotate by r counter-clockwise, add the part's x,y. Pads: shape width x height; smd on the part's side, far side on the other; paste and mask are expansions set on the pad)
157T [mm]
  rect 2.4x3 smd: 1(0,0) 2(4.86,0)
  silkscreen extent -1.4,-1.65 6.26,1.65
0603_1 [mil]
  rect 42x35 smd: 1(0,0) 2(70,0)
  silkscreen extent -30,-30 100,30
0805 [mil]
  rect 60x50 smd: 1(0,0) 2(-90,0)
  silkscreen extent -140,-45 50,45
0805_1 [mil]
  rect 60x50 smd: 1(0,0) 2(90,0)
  silkscreen extent -108,-45 140,50
0805_2 [mil]
  rect 60x50 smd: 1(0,0) 2(90,0)
  silkscreen extent -50,-45 140,100
1206 [mil]
  rect 60x60 smd: 1(0,0) 2(135,0)
  silkscreen extent -50,-50 185,50
1210_1 [mil]
  rect 60x100 smd: 1(0,0) 2(135,0)
  silkscreen extent -50,-70 185,70
2010 [mil]
  rect 60x100 smd: 1(0,0) 2(215,0)
  silkscreen extent -50,-70 265,70
2512_1 [mil]
  rect 110x125 smd: 1(0,0) 2(240,0)
  silkscreen extent -70,-65 310,65
3216 [mil]
  rect 60x50 smd: 1(-50,-5) 2(60,-5)
  silkscreen extent -100,-50 110,40
7243 [mil]
  rect 120x100 smd: 1(0,0) 2(-290,0)
  silkscreen extent -370,-70 85,70
CRYSTAL-SMD [mil]
  rect 43.31x80 smd: 1(0,0) 2(0,120) 3(-62.99,120) 4(-62.99,0)
  silkscreen extent -102,-50 70,170
D214A [mil]
  rect 80x100 smd: 1(-100,0) 2(100,0)
  silkscreen extent -160,-100 100,80
DECA-3 [mm]
  rect 2.5x3 hole 1.5: 1(-10.16,0)
  oval 2.5x3 hole 1.27: 2(-5.08,0) 3(0,0)
  silkscreen extent -13.72,-2.03 3.56,10.16
DIP6 [mil]
  rect 60x60 hole 35: 1(0,0)
  round 60 hole 35: 2(100,0) 3(200,0) 4(300,0) 5(400,0) 6(500,0)
  silkscreen extent -96,-112 593,112
DIP-6 [mil]
  oct 65x65 hole 42: 1(-260,55)
  round 65 hole 42: 2(-260,-45) 3(-260,-145) 4(40,-145) 5(40,-45) 6(40,55)
  silkscreen extent -330,-245 110,155
DO-214AB [mm]
  rect 3x4 smd: 1(0,0) 2(-7.112,0)
  silkscreen extent -7.2,-3.56 2.03,3.15
DUB-8 [mil]
  rect 100x47 smd: 1(-179,81)
  oval 100x47 smd: 2(-179,-19) 3(-179,-119) 4(-179,-219) 5(166,-219) 6(166,-119) 7(166,-19)
  oval 100x47.24 smd: 8(166,81)
  silkscreen extent -117,-262 109,138
"MC 1.5/3-G-3.81" [mm]
  round 2.2 hole 1.2: 1(0,0) 2(3.81,0) 3(7.62,0)
  silkscreen extent -2.6,-8 10.29,1.52
"MC 1.5/4-G-3.81" [mm]
  round 2.2 hole 1.2: 1(2.6,0) 2(6.41,0) 3(10.22,0) 4(14.03,0)
  silkscreen extent 0,-8 16.63,1.52
"MC 1.5/8-G-3.81" [mm]
  round 2.2 hole 1.2: 1(0,0) 2(3.81,0) 3(7.62,0) 4(11.43,0) 5(15.24,0) 6(19.05,0) 7(22.86,0) 8(26.67,0)
  silkscreen extent -2.83,-8 29.46,1.52
MCDN-2 [mm]
  round 2.2 hole 1.3: 1(0,0) 2(3.5,0) 3(0,-3.5) 4(3.5,-3.5)
  silkscreen extent -2.54,-12.8 6.04,1.33
MCDN-3 [mm]
  round 2.2 hole 1.3: 1(0,-3.5) 2(3.5,-3.5) 3(7,-3.5) 4(0,0) 5(3.5,0) 6(7,0)
  silkscreen extent -2.54,-12.8 9.54,1.33
RAD-0.3 [mil]
  round 95 hole 55: 1(0,0) 2(0,251.97)
  silkscreen extent -75,-75 75,325
"RB 5.0MM/12.5MM_NOPOST" [mil]
  round 75 hole 40: 1(196.85,0) 2(0,0)
  silkscreen extent -148,-246 398,246
RYPA1A-24 [mil]
  round 70 hole 35: 1(0,0) 2(0,200) 3(0,600) 4(0,700)
  silkscreen extent -160,-60 60,760
SMD-6.6*7.7 [mil]
  rect 50x130 smd: 1(0,0) 2(0,-220)
  silkscreen extent -135,-240 135,20
SO-8 [mil]
  rect 80x24 smd: 1(-114,69)
  oval 80x24 smd: 2(-114,19) 3(-114,-31) 4(-114,-81) 5(106,-81) 6(106,-31) 7(106,19) 8(106,69)
  silkscreen extent -54,-106 46,94
SOD-123 [mm]
  rect 0.91x1.22 smd: 1(0,0) 2(3.25,0)
  silkscreen extent -0.51,-1.52 3.13,1
SOP10 [mil]
  rect 80x30 smd: 1(0,0)
  oval 80x30 smd: 2(0,-50) 3(0,-100) 4(0,-150) 5(0,-200) 6(543.31,-200) 7(543.31,-150) 8(543.31,-100) 9(543.31,-50) 10(543.31,0)
  rect 400x530 smd: 11(273.19,-100)
  silkscreen extent -7,-225 480,72
SOP14 [mil]
  rect 80x24 smd: 1(0,0)
  oval 80x24 smd: 2(0,-50) 3(0,-100) 4(0,-150) 5(0,-200) 6(0,-250) 7(0,-300) 8(220,-300) 9(220,-250) 10(220,-200) 11(220,-150) 12(220,-100) 13(220,-50) 14(220,0)
  silkscreen extent 60,-325 160,25
SOP16 [mil]
  oval 80x24 smd: 1(0,0) 2(0,-50) 3(0,-100) 4(0,-150) 5(0,-200) 6(0,-250) 7(0,-300) 8(0,-350) 9(220,-350) 10(220,-300) 11(220,-250) 12(220,-200) 13(220,-150) 14(220,-100) 15(220,-50) 16(220,0)
  silkscreen extent 60,-375 160,25
SOP38 [mm]
  rect 3.3x6.6 smd: 0(0,0)
  rect 1.4x0.24 smd: 1(-3.535,4.5) 2(-3.535,4) 3(-3.535,3.5) 4(-3.535,3) 5(-3.535,2.5) 6(-3.535,2) 7(-3.535,1.5) 8(-3.535,1) 9(-3.535,0.5) 10(-3.535,0) 11(-3.535,-0.5) 12(-3.535,-1) 13(-3.535,-1.5) 14(-3.535,-2) 15(-3.535,-2.5) 16(-3.535,-3) 17(-3.535,-3.5) 18(-3.535,-4) 19(-3.535,-4.5) 20(3.535,-4.5) 21(3.535,-4) 22(3.535,-3.5) 23(3.535,-3) 24(3.535,-2.5) 25(3.535,-2) 26(3.535,-1.5) 27(3.535,-1) 28(3.535,-0.5) 29(3.535,0) 30(3.535,0.5) 31(3.535,1) 32(3.535,1.5) 33(3.535,2) 34(3.535,2.5) 35(3.535,3) 36(3.535,3.5) 37(3.535,4) 38(3.535,4.5)
  silkscreen extent -2.39,-5.08 2.41,5.21
SOP-4-2 [mil]
  rect 80x25 smd: 1(0,0)
  oval 80x25 smd: 2(0,-100) 3(240,-100) 4(240,0)
  silkscreen extent 60,-100 180,10
SOT-23-DIODE [mil]
  rect 36x36 smd: 1(0,0) 2(-75,0)
  rect 36x50 smd: 3(-38,-80)
  silkscreen extent -95,-85 20,5
SSO-20 [mil]
  rect 12x48 smd: 1(0,0)
  oval 12x48 smd: 2(25.59,0) 3(51.18,0) 4(76.77,0) 5(102.36,0) 6(127.95,0) 7(153.54,0) 8(179.13,0) 9(204.72,0) 10(230.31,0) 11(230.31,314.96) 12(204.72,314.96) 13(179.13,314.96) 14(153.54,314.96) 15(127.95,314.96) 16(102.36,314.96) 17(76.77,314.96) 18(51.18,314.96) 19(25.59,314.96) 20(0,314.96)
  silkscreen extent -20,47 240,267
TO-220 [mil]
  round 100 hole 40: 0(-100,700)
  rect 62x72 hole 45: 1(-200,0)
  oval 62x82 hole 45: 2(-100,0) 3(0,0)
  silkscreen extent -300,60 100,800
TQFP-64 [mm]
  rect 2x0.25 smd: 1(-0.127,0) 2(-0.127,-0.5) 3(-0.127,-1) 4(-0.127,-1.5) 5(-0.127,-2) 6(-0.127,-2.5) 7(-0.127,-3) 8(-0.127,-3.5) 9(-0.127,-4) 10(-0.127,-4.5) 11(-0.127,-5) 12(-0.127,-5.5) 13(-0.127,-6) 14(-0.127,-6.5) 15(-0.127,-7) 16(-0.127,-7.5) 33(11.527,-7.5) 34(11.527,-7) 35(11.527,-6.5) 36(11.527,-6) 37(11.527,-5.5) 38(11.527,-5) 39(11.527,-4.5) 40(11.527,-4) 41(11.527,-3.5) 42(11.527,-3) 43(11.527,-2.5) 44(11.527,-2) 45(11.527,-1.5) 46(11.527,-1) 47(11.527,-0.5) 48(11.527,0)
  rect 0.25x2 smd: 17(1.95,-9.577) 18(2.45,-9.577) 19(2.95,-9.577) 20(3.45,-9.577) 21(3.95,-9.577) 22(4.45,-9.577) 23(4.95,-9.577) 24(5.45,-9.577) 25(5.95,-9.577) 26(6.45,-9.577) 27(6.95,-9.577) 28(7.45,-9.577) 29(7.95,-9.577) 30(8.45,-9.577) 31(8.95,-9.577) 32(9.45,-9.577) 49(9.45,2.077) 50(8.95,2.077) 51(8.45,2.077) 52(7.95,2.077) 53(7.45,2.077) 54(6.95,2.077) 55(6.45,2.077) 56(5.95,2.077) 57(5.45,2.077) 58(4.95,2.077) 59(4.45,2.077) 60(3.95,2.077) 61(3.45,2.077) 62(2.95,2.077) 63(2.45,2.077) 64(1.95,2.077)
  silkscreen extent 1.27,-8.13 10.14,0.74
WE-CMB#1 [mil]
  rect 130x59.05 smd: 1(0,0) 2(0,95) 3(310,100) 4(310,-5)
  silkscreen extent -35,-55 345,145
WE-CMB#2 [mil]
  rect 130x59.05 smd: 1(0,0) 2(0,105) 3(310,105) 4(310,0)
  silkscreen extent -35,-48 345,152
ZDL10-24T050505 [mm]
  oval 2.5x3 hole 1.2: 1(0,0) 2(0,10.16) 3(0,15.24) 4(0,25.4) 5(45.72,27.94) 6(45.72,22.86) 7(45.72,17.78) 8(45.72,7.62) 9(45.72,2.54) 10(45.72,-2.54)
  silkscreen extent -2.52,-7.58 48.28,33.02

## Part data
C100 C104 C105 C107 C108 C110 C114 C115 C116 C119 C402 C403 C404 C408 C414 C502 C503 C504 C508 C514 C612 C613 C800 C801 C802 C803 C804 C805 C806 C807 C808 C809 C810 C811 C812 C813 C814 C817 C818 C900 C901 C902: library part CAP, "Capacitor"
C101 C102 C109 C111 C117 C120 C401 C413 C501 C513 C816: library part CAPACITOR, "Capacitor"
C112 C113 C118 C400 C405 C406 C407 C409 C410 C411 C412 C415 C416 C500 C505 C506 C507 C509 C510 C511 C512 C515 C516: library part Cap, "Capacitor"
C200 C201 C202 C205 C300 C302 C303 C304 C305 C600 C601 C602 C603 C604 C605 C606 C607 C608 C609 C610 C611: library part CAP(1)
D100 D104 D900 D901: library part "DIODE SCHOTTKY", "Schottky Diode"
D101 D102 D103 D105: "Typical INFRARED GaAs LED"
D200 D201: library part "D Schottky", "Schottky Diode"
D400 D401 D500 D501: library part LED2, "LED RED FACE UP 1206"
D602 D603 D606 D607 D610 D611 D614 D615 D618 D619 D622 D623: library part DIODE, "Diode"
D800: library part LED0, "Typical INFRARED GaAs LED"
D801: library part SP0502
F100: "Fuse"
J700 J701 J702 J703 J704 J705: library part CON6'
J706: library part CON8, "Connector"
J707 J712 J713 J714 J715: library part CON4, "Connector"
J708 J709 J710 J711: "Connector"
J800: library part CON6, "Connector"
K300 K301 K302 K303: library part RELAY-SPST
L100 L800 R100 R101 R102 R103 R106 R107 R108 R109 R110 R112 R113 R114 R115 R200 R201 R202 R203 R204 R205 R206 R207 R220 R221 R222 R300 R301 R304 R305 R306 R309 R313 R315 R318 R319 R320 R323 R404 R405 R413 R414 R504 R505 R513 R514 R600 R601 R602 R603 R604 R605 R606 R607 R608 R609 R610 R611 R612 R613 R614 R615 R616 R617 R618 R619 R620 R621 R622 R623 R624 R625 R626 R627 R628 R629 R630 R631 R632 R633 R634 R635 R636 R637 R638 R639 R640 R641 R642 R643 R644 R645 R646 R647 R648 R649 R650 R651 R652 R653 R654 R655 R656 R657 R658 R659 R800 R801 R802 R803 R804 R805 R806 R807 R808 R809 R810 R811 R812 R813 R814 R815 R816 R817 R818 R819 R820 R900 R901 R902 R903 R904: library part RES1
R111: library part RES4
R208 R209 R700 R701 R702 R703 R704 R705 R706 R707 R708 R709 R710 R711: library part RES2
R400 R401 R500 R501: library part RES1, "RES 3.3K OHM 1/10W 5% 0603 SMD"
R402 R403 R406 R407 R408 R411 R412 R415 R416 R417 R418 R502 R503 R506 R507 R508 R511 R512 R515 R516 R517 R518: library part Res1, "RES 3.3K OHM 1/10W 5% 0603 SMD"
R409 R410 R509 R510: library part Res1, "Resistor"
SW800: "DIP Switch"
T800 T900: library part TRANS1
U200 U201 U205 U300 U302 U303 U305 U902: library part Optoisolator1, "4-Pin Phototransistor Optocoupler"
U400 U500: "Pre Driver Stepper Motor Controller"
U600 U601 U603 U604 U605 U606 U607 U608 U610 U611 U612 U613: library part OPTOISO1, "Optoisolator"
U800: library part AT25M01
U802: library part 74LVC245
U900: "Low-Power, Slew-Rate-Limited RS-485/RS-422 Transceiver"
Y800: library part CRYSTAL

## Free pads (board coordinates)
  round 260 hole 177: ""(-4173.23,0) ""(-4173.23,6653.54) ""(0,0) ""(0,6653.54)
  round 60 smd: ""(-4144.45,386.73) ""(-284.45,6616.73)
  round 60 smd far side: ""(-4144.45,386.73) ""(-284.45,6616.73)
  oct 80x80 smd far side: ""(-439.45,2660.73) ""(-239.45,3824.73) ""(-223.45,6148.73)
  oct 90x90 smd far side: ""(-403.45,566.73) ""(-403.45,763.58) ""(-242.6,2660.73) ""(-42.6,3824.73) ""(-26.6,6148.73)
  oct 100x80 smd far side: ""(312.55,4025.62)

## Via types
v1: diameter 25, hole 15, Top Layer to Bottom Layer, 303 vias
v2: diameter 25, hole 12, Top Layer to Bottom Layer, 94 vias
v3: diameter 50, hole 25, Top Layer to Bottom Layer, 71 vias
v4: diameter 30, hole 16, Top Layer to Bottom Layer, 71 vias
v5: diameter 12, hole 8, Top Layer to Bottom Layer, 25 vias
v6: diameter 25, hole 12, Top Layer to Bottom Layer, tented both sides, 24 vias
v7: diameter 35, hole 20, Top Layer to Bottom Layer, 7 vias
v8: diameter 20, hole 12, Top Layer to Bottom Layer, 3 vias
v9: diameter 8, hole 5, Top Layer to Bottom Layer, 2 vias
v10: diameter 35, hole 25, Top Layer to Bottom Layer, 1 vias

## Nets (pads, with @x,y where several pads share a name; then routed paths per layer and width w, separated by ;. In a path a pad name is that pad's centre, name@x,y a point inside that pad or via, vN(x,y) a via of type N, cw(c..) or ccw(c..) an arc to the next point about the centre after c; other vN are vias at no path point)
5VGND: C108.2 C109.2 C112.1 C805.1 C806.2 C808.2 C816.2 D801.3 J712.3 J713.3 POWER.9 R100.2 R106.2 R107.1 U804.5 | length 3578.3
  Top Layer w20: U804.5@-3517.45,4712.73 v1(-3517.45,4765.73) v1@-3516.45,4764.73
  Top Layer w30: POWER.9@-3590,2410 -3590,2588 -3814,2812 -3814,3128 -3692,3250 -3692,3734 -3406,4020 v1(-3406,4396)
  Bottom Layer w20: v1(-3776,4398) D801.3@-3776,4450 ; v1@-3516.45,4764.73 C808.2@-3516.45,4603.73 -3471.45,4603.73 -3451.45,4623.73 C816.2@-3406.45,4623.73
  Bottom Layer w25: -3878,5385.56 R100.2@-3878,5520 ; C108.2@-3660,2670 -3590,2600 POWER.9@-3590,2410 ; C109.2@-3640,2575 -3591,2575
  Bottom Layer w40: R107.1@-4120,5326 R106.2@-4120,5436 ; C112.1@-4120,5537.18 R106.2@-4120,5436 ; v1(-4010,5436) R106.2@-4120,5436 ; C806.2@-3920.73,5379.38 v1@-3828.73,5379.38 ; v1@-3828.73,5380.55 v1@-3828.73,5379.38 ; C805.1@-3770.73,5379.38 v1@-3828.73,5379.38
  other v1: -3406,4340 -3866,5379.38 -3824,5379.38 -4052,5436
24VGND: C100.2 C101.2 C102.2 C104.2 C105.2 C107.1 C201.2 C304.2 D100.1 D200.1 D201.1 D600.2 D601.2 D604.2 D605.2 D608.2 D609.2 D612.2 D613.2 D616.2 D617.2 D620.2 D621.2 J700.2 J700.5 J701.2 J701.5 J702.2 J702.5 J703.2 J703.5 J704.2 J704.5 J705.2 J705.5 J707.2 J707.4 J711.2 POWER.3 R102.2 R103.1 R203.1 R207.1 R304.1 R309.1 R318.1 R323.1 R608.2 R609.2 R618.2 R619.2 R628.2 R629.2 R638.2 R639.2 R648.2 R649.2 R658.2 R659.2 U108.8 U203.5 | length 8315.6
  Top Layer w20: v1@-3514.45,5841.73 v1(-3514.45,5840.91) D621.2@-3514.45,5969.73 ; v1(-3304.45,5840.91) D617.2@-3304.45,5969.73 ; v1(-3099.45,5840.91) D613.2@-3099.45,5969.73 ; v1(-2889.45,5840.91) D609.2@-2889.45,5969.73 ; v1(-2679.45,5840.91) D605.2@-2679.45,5969.73 ; v1(-2464.45,5840.91) D601.2@-2464.45,5969.73 ; R203.1@-2406,1362 v1(-2328,1362) ; v1(-2259.45,5840.91) D620.2@-2259.45,5969.73 ; R207.1@-2138,1360 v1(-2060,1360) ; v1(-2044.45,5840.91) D616.2@-2044.45,5969.73 ; v1(-1834.45,5840.91) D612.2@-1834.45,5969.73 ; v1(-1619.45,5840.91) D608.2@-1619.45,5969.73 ; v1(-1404.45,5840.91) D604.2@-1404.45,5969.73 ; v1(-1189.45,5840.91) D600.2@-1189.45,5969.73
  Top Layer w25: v1(-3920,1092) R323.1@-3920,1160 ; v1(-3590,1092) R318.1@-3590,1160 ; v1(-3250,1092) R309.1@-3250,1160 ; v1(-2910,1092) R304.1@-2910,1160 ; v4(-2673.45,531.45) C201.2@-2673.45,586.73 ; v4(-2569.73,431.73) D200.1@-2514.45,431.73 ; v4(-2269.73,431.73) D201.1@-2214.45,431.73 ; U203.5@-2263.45,586.73 v4(-2208.16,586.73)
  Top Layer w60: v1(-4029.45,5848) v4(-4029.45,5920) C101.2@-4029.45,6031.73 ; C102.2@-4028.45,5734.45 v1@-4028.45,5841.73
  Bottom Layer w20: v1@-4029.45,5849.38 R102.2@-3880.73,5849.38 ; U108.8@-3089.45,1487.73 v1(-3035.45,1487.73) -3005.45,1457.73 C304.2@-3005.45,1412.73
  Bottom Layer w50: C104.2@-4090,5920 v4(-4029.45,5920) ; v1@-4029.45,5778 -4029.45,5849.38 v4(-4029.45,5920) ; D100.1@-3969.45,6141.73 -3969.45,6128.55 -4029.45,6068.55 v4(-4029.45,5980) v4(-4029.45,5920) ; C100.2@-3789.45,6381.73 C107.1@-3669.45,6381.73 R103.1@-3669.45,6286.73 ; v7(-3688,5740) -3586,5638 -3586,5132 -3388,4934 -3186,4934 -2992,4740 -2992,4308 POWER.3@-3090,4210 ; v1@-3582,5840.91 v1(-3514.45,5840.91) v1(-3304.45,5840.91) v1(-3099.45,5840.91) v1(-2889.45,5840.91) v1(-2679.45,5840.91) v1(-2464.45,5840.91) v1(-2259.45,5840.91) v1(-2044.45,5840.91) v1(-1834.45,5840.91) v1(-1619.45,5840.91) v1(-1404.45,5840.91) v1(-1189.45,5840.91) -1095.27,5840.91 R608.2@-1094.45,5841.73
  Bottom Layer w60: C105.2@-4088,5778 v1@-4029.45,5778 ; -3729.45,6383.18 -3729.45,6422
  Bottom Layer w80: -3729.45,6422 J711.2@-3729.45,6606.73 v4(-3729.45,6674) v4@-3729.45,6734
  other v1: -4028.45,5780 -3580,5840
  other v4: -3729.45,6510 -3730,6738
  other v7: -3642,5694 -3620,5754
485_EN: U802.9 U902.2 | length 2106.3
  Top Layer w10: U802.9@-3318,2100.73 -3245.28,2100.73 -3094,2252 -3094,3038 v1(-3026,3106)
  Bottom Layer w10: v1@-3026,3104 v1(-3026,3106) -3026,3280 -2740,3566 -2740,3794 -2694,3840 U902.2@-2630,3840
485A: J714.2 J715.2 T900.3 | length 1775.5
  Top Layer w25: T900.3@-4235,2340 -4235,2807.09 J715.2@-4094.45,2947.64 ; J715.2@-4125.26,2947.64 cw(c-4199.63,2947.64) -4147.04,2895.05 cw(c-4094.45,2842.46) J715.2@-4094.45,2916.83
  Bottom Layer w25: J715.2@-4125.26,2947.64 ccw(c-4199.63,2947.64) -4147.04,3000.23 ccw(c-4094.45,3052.82) J715.2@-4094.45,2978.44 ; J714.2@-4125.26,3627.64 cw(c-4199.63,3627.64) -4147.04,3575.05 cw(c-4094.45,3522.46) J714.2@-4094.45,3596.83 ; J715.2@-4094.45,2947.64 -4190,3043.19 -4190,3532.09 J714.2@-4094.45,3627.64
485B: J714.1 J715.1 T900.4 | length 2354.3
  Top Layer w25: T900.4@-4130,2340 -4130,2260 -4180,2210 -4264,2210 -4314,2260 -4314,2878.09 J715.1@-4094.45,3097.64 -3986,3206.09 -3986,3669.19 J714.1@-4094.45,3777.64 ; J715.1@-4125.26,3097.64 cw(c-4199.63,3097.64) -4147.04,3045.05 cw(c-4094.45,2992.46) J715.1@-4094.45,3066.83 ; J715.1@-4094.45,3128.44 ccw(c-4094.45,3202.82) -4041.86,3150.23 ccw(c-3989.27,3097.64) J715.1@-4063.64,3097.64 ; J714.1@-4094.45,3746.83 cw(c-4094.45,3672.46) -4041.86,3725.05 cw(c-3989.27,3777.64) J714.1@-4063.64,3777.64
485G1: C116.2 C117.2 C118.1 C119.2 C120.2 C900.1 C902.1 D900.1 D901.1 J714.3 J715.3 POWER.5 R113.2 R114.1 R115.2 R903.1 U900.5 U901.5 U902.3 | length 2655.1
  Bottom Layer w20: v1@-4034,2070 R115.2@-3940,2070 ; v1(-3870,3346) D900.1@-3870,3410 ; D901.1@-3870,3946 v1(-3870,4010) ; C900.1@-3610,3534 v1(-3546,3534) ; C902.1@-3610,3844 v1(-3610,3908) ; v1(-3446,3882) R903.1@-3382,3882 ; v1(-3236,3580) U900.5@-3236,3619 ; v1(-2939,3840) U902.3@-2870,3840 ; U901.5@-2866,3619 v1(-2797,3619)
  Bottom Layer w30: C119.2@-3080,3540 -3080,3475 C120.2@-3060,3455 ; v1(-2940,3442) -3028,3442 -3082,3388 -3082,2900 -2988,2806 -2768,2806 -2590,2628 POWER.5@-2590,2410 ; C117.2@-2650,2575 -2591,2575
  Bottom Layer w40: R114.1@-3860,4350 R113.2@-3860,4240 C118.1@-3860,4130 -3752,4022 v1@-3688,4022
  other v1: -4032,2070 -2994,3442 -3688,4020 -3748,4022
